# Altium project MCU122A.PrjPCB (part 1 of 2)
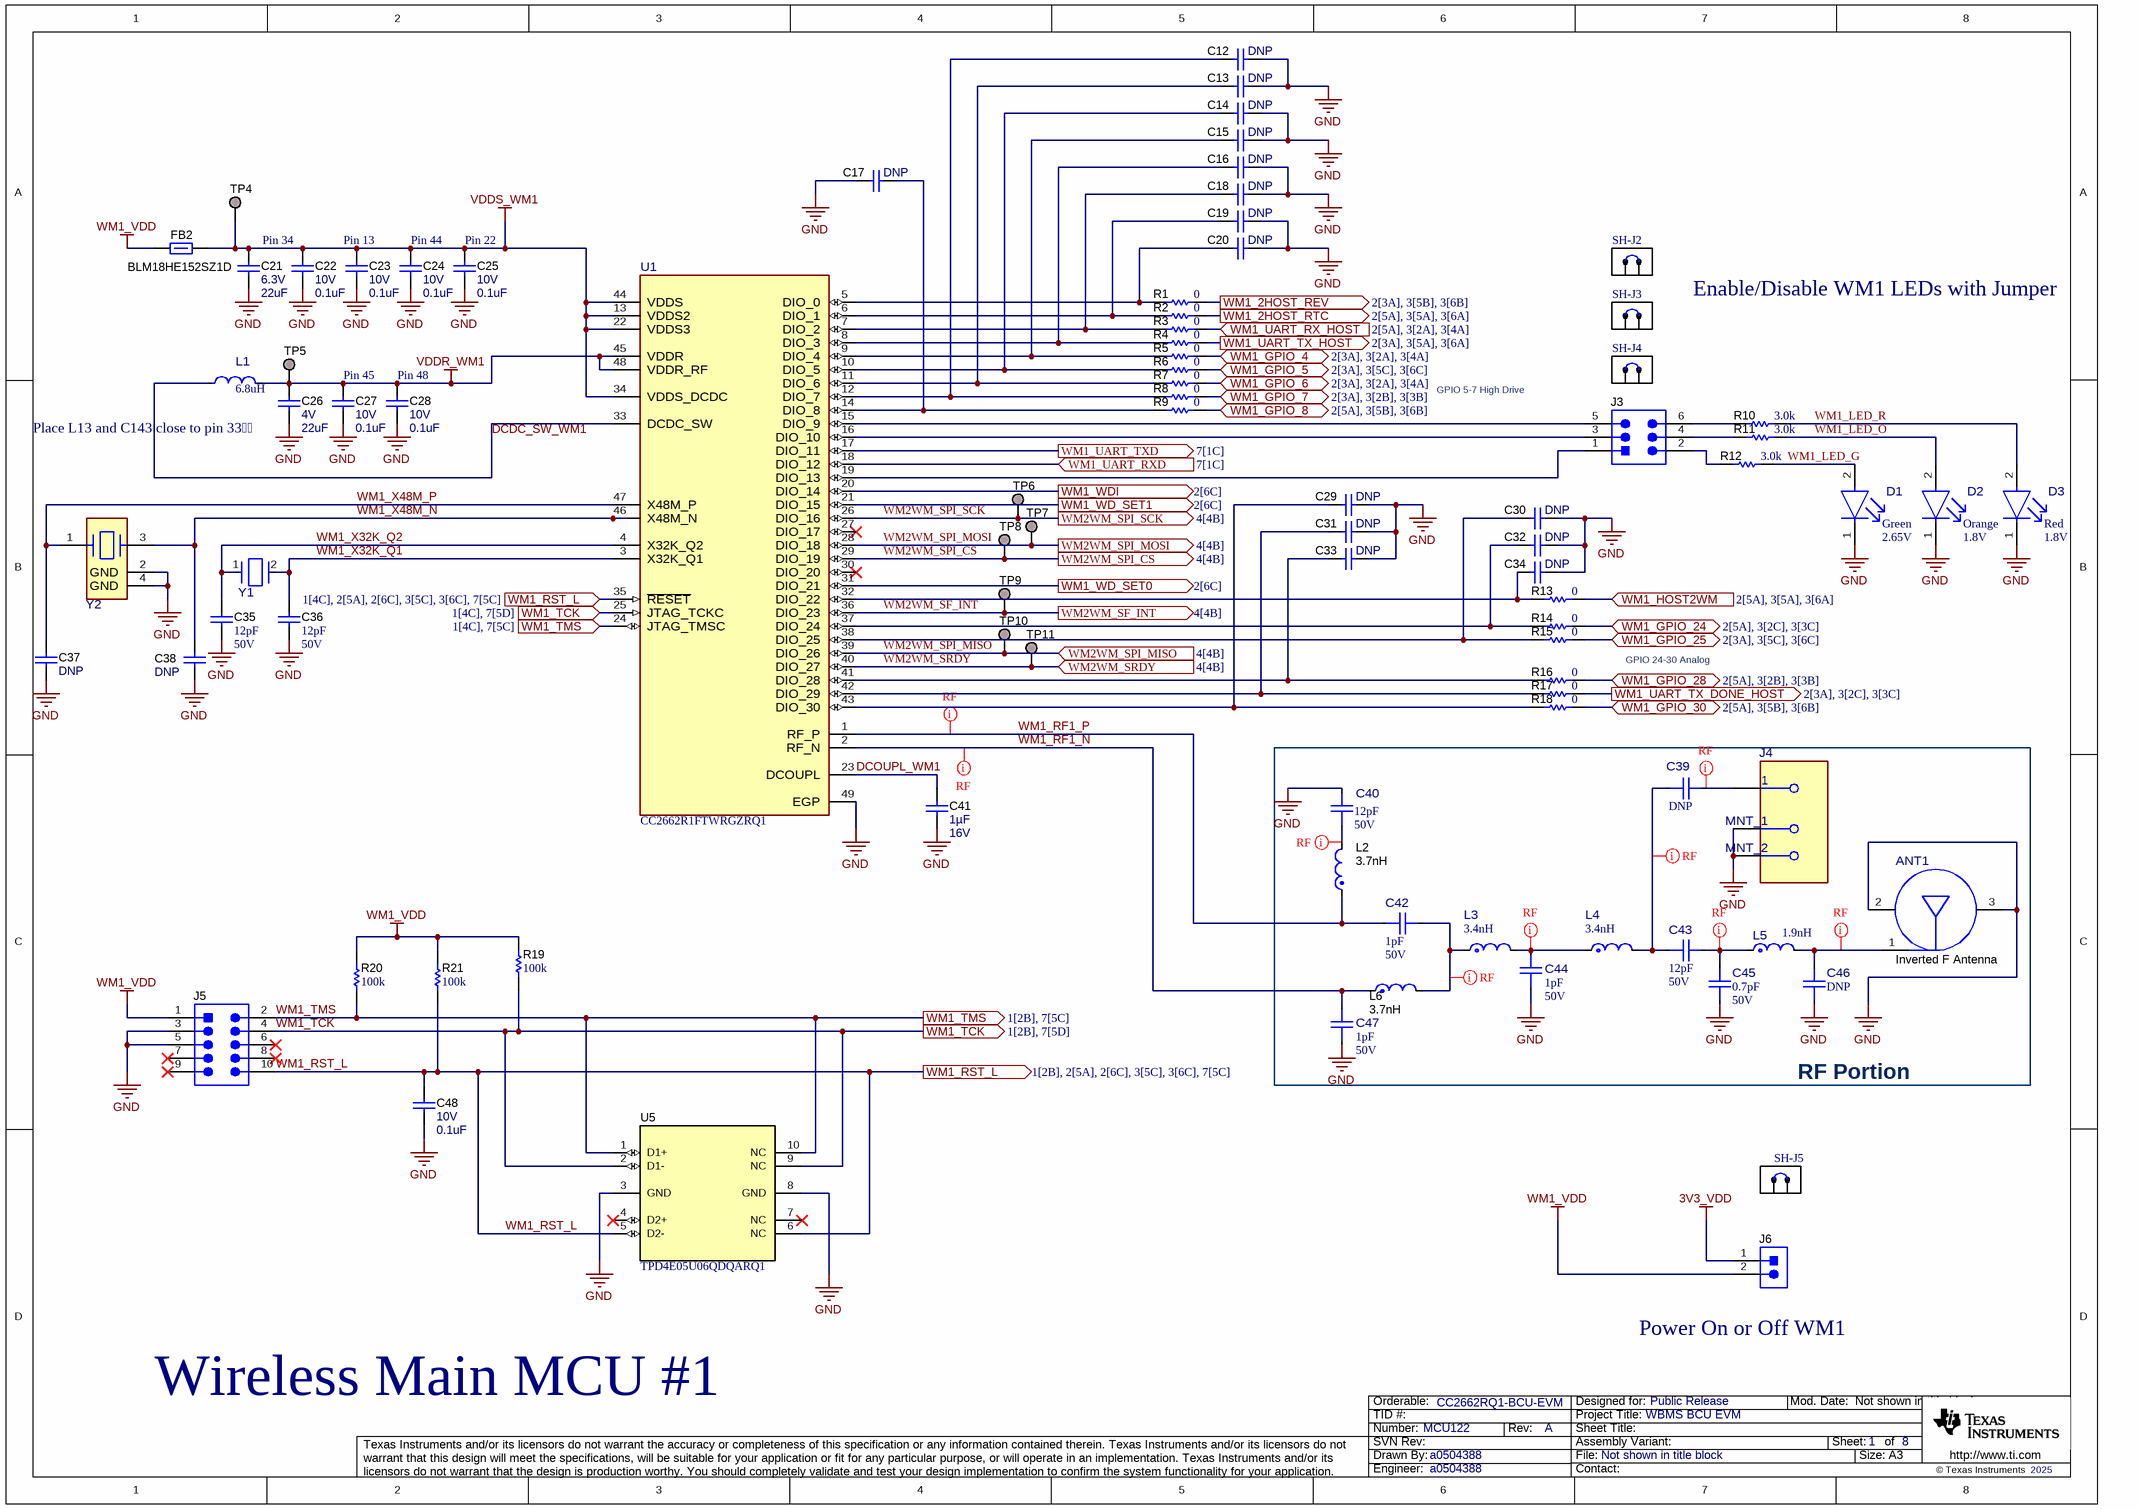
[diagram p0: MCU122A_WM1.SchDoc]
SCH_Rev: A; PRJ_Title: WBMS BCU EVM; PRJ_Number: MCU122; PRJ_Engineer: a0504388; PRJ_Customer: Public Release; PCB_Rev: A; EVM_orderable: CC2662RQ1-BCU-EVM; DrawnBy: a0504388; CopyrightYear: 2025
8 sheets, 257 parts. Net scope: flat (ports and power ports of the same name join across sheets).
Board file: MCU122A.PcbDoc
Sheets:
  MCU122A_WM1.SchDoc
  MCU122A_WM1_GPIO_Header.SchDoc
  MCU122A_WM1_ESD.SchDoc
  MCU122A_WM2.SchDoc
  MCU122A_WM2_GPIO_Header.SchDoc
  MCU122A_WM2_ESD.SchDoc
  MCU122A_Connector_PWR.SchDoc
  MCU122A_Hardware.SchDoc

## Sheet MCU122A_WM1.SchDoc
size A3; Date: Not shown in title block; ApprovedBy: Not shown in title block; CheckedBy: Not shown in title block; Author: Not shown in title block; CompanyName: Not shown in title block; Engineer: Andrew Lugo; Organization: Not shown in title block; Address1: Not shown in title block; Address2: Not shown in title block; Address3: Not shown in title block; Address4: Not shown in title block; DocumentNumber: 1; Revision: Use project parameter SCH_Rev; SheetNumber: 1; SheetTotal: 8; PageSetup: Record=PageOptions¦CenterHorizontal=True¦CenterVertical=True¦PrintScale=0.69¦XCorrection=1.00¦YCorrection=1.00¦PrintKind=0¦BorderSize=5000000¦LeftOffset=0¦BottomOffset=0¦Orientation=2¦PaperLength=1000¦PaperWidth=1000¦Scale=100¦PaperSource=15¦PrintQuality=600¦MediaType=1¦DitherType=10¦PaperKind=Letter¦PrintScaleMode=1

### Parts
ANT1  Inverted F Antenna  [0-MFG]
C12  ValueDisplayed: DNP  [0402]  (hidden comment: GCM155R71A104KA55D)
C13  ValueDisplayed: DNP  [0402]  (hidden comment: GCM155R71A104KA55D)
C14  ValueDisplayed: DNP  [0402]  (hidden comment: GCM155R71A104KA55D)
C15  ValueDisplayed: DNP  [0402]  (hidden comment: GCM155R71A104KA55D)
C16  ValueDisplayed: DNP  [0402]  (hidden comment: GCM155R71A104KA55D)
C17  ValueDisplayed: DNP  [0402]  (hidden comment: GCM155R71A104KA55D)
C18  ValueDisplayed: DNP  [0402]  (hidden comment: GCM155R71A104KA55D)
C19  ValueDisplayed: DNP  [0402]  (hidden comment: GCM155R71A104KA55D)
C20  ValueDisplayed: DNP  [0402]  (hidden comment: GCM155R71A104KA55D)
C21  VDC_V: 6.3V  ValueDisplayed: 22uF  [0805_HV]  (hidden comment: GCM21BD70J226ME36L)
C22  VDC_V: 10V  ValueDisplayed: 0.1uF  [0402]  (hidden comment: GCM155R71A104KA55D)
C23  VDC_V: 10V  ValueDisplayed: 0.1uF  [0402]  (hidden comment: GCM155R71A104KA55D)
C24  VDC_V: 10V  ValueDisplayed: 0.1uF  [0402]  (hidden comment: GCM155R71A104KA55D)
C25  VDC_V: 10V  ValueDisplayed: 0.1uF  [0402]  (hidden comment: GCM155R71A104KA55D)
C26  VDC_V: 4V  ValueDisplayed: 22uF  [0603]  (hidden comment: AMK107BBJ226MAHT)
C27  VDC_V: 10V  ValueDisplayed: 0.1uF  [0402]  (hidden comment: GCM155R71A104KA55D)
C28  VDC_V: 10V  ValueDisplayed: 0.1uF  [0402]  (hidden comment: GCM155R71A104KA55D)
C29  ValueDisplayed: DNP  [0402]  (hidden comment: GCM155R71A104KA55D)
C30  ValueDisplayed: DNP  [0402]  (hidden comment: GCM155R71A104KA55D)
C31  ValueDisplayed: DNP  [0402]  (hidden comment: GCM155R71A104KA55D)
C32  ValueDisplayed: DNP  [0402]  (hidden comment: GCM155R71A104KA55D)
C33  ValueDisplayed: DNP  [0402]  (hidden comment: GCM155R71A104KA55D)
C34  ValueDisplayed: DNP  [0402]  (hidden comment: GCM155R71A104KA55D)
C35  ValueDisplayed: 12pF  VDC_V: 50V  [0402]  (hidden comment: GCM1555C1H120JA16J)
C36  ValueDisplayed: 12pF  VDC_V: 50V  [0402]  (hidden comment: GCM1555C1H120JA16J)
C37  ValueDisplayed: DNP  [0402]  (hidden comment: GCM1555C1H120JA16J)
C38  ValueDisplayed: DNP  [0402]  (hidden comment: GCM1555C1H120JA16J)
C39  ValueDisplayed: DNP  [FP-GCQ0335C1H1R0BB01D_0201-MFG]  (hidden comment: GCQ0335C1H1R0BB01D)
C40  ValueDisplayed: 12pF  VDC_V: 50V  [FP-GCQ0335C1H120GB01D_0201-MFG]  (hidden comment: GCQ0335C1H120GB01D)
C41  Cap_F: 1µF  VDC_V: 16V  [0603]  (hidden comment: GCM188R71C105KA64D)
C42  ValueDisplayed: 1pF  VDC_V: 50V  [FP-GCQ0335C1H1R0WB01D_0201-MFG]  (hidden comment: GCQ0335C1H1R0WB01D)
C43  ValueDisplayed: 12pF  VDC_V: 50V  [FP-GCQ0335C1H120GB01D_0201-MFG]  (hidden comment: GCQ0335C1H120GB01D)
C44  ValueDisplayed: 1pF  VDC_V: 50V  [FP-GCQ0335C1H1R0WB01D_0201-MFG]  (hidden comment: GCQ0335C1H1R0WB01D)
C45  ValueDisplayed: 0.7pF  VDC_V: 50V  [FP-GCQ0335C1HR70WB01D_0201-MFG]  (hidden comment: GCQ0335C1HR70WB01D)
C46  ValueDisplayed: DNP  [FP-GCQ0335C1H1R0BB01D_0201-MFG]  (hidden comment: GCQ0335C1H1R0BB01D)
C47  ValueDisplayed: 1pF  VDC_V: 50V  [FP-GCQ0335C1H1R0WB01D_0201-MFG]  (hidden comment: GCQ0335C1H1R0WB01D)
C48  VDC_V: 10V  ValueDisplayed: 0.1uF  [0402]  (hidden comment: GCM155R71A104KA55D)
D1  Color: Green  Vf_V: 2.65V  [FP-APHHS1005LZGCK-V_0402-MFG]  (hidden comment: APHHS1005LZGCK-V)
D2  Color: Orange  Vf_V: 1.8V  [FP-APHHS1005LSECK/J4-PF_0402-MFG]  (hidden comment: APHHS1005LSECK/J4-PF)
D3  Color: Red  Vf_V: 1.8V  [FP-APHHS1005LSECK/J3-PF_0402-MFG]  (hidden comment: APHHS1005LSECK/J3-PF)
FB2  BLM18HE152SZ1D  [0603]
J3  TSW-103-07-G-D  [TSW-103-07-G-D]  (value not drawn)
J4  132134-10  [FP-132134-10_SMA-MFG]  (value not drawn)
J5  FTSH-105-01-F-DV-K  [Samtec_FTSH-105-01-x-DV-K]  (value not drawn)
J6  TSW-102-07-G-S  [TSW-102-07-G-S]  (value not drawn)
L1  value 6.8uH  [FP-MLZ2012N6R8LTD25_0805-MFG]  (hidden comment: MLZ2012N6R8LTD25)
L2  value 3.7nH  [FP-LQP03TN3N7BZ2J_0603-MFG]  (hidden comment: LQP03TN3N7BZ2J)
L3  value 3.4nH  [FP-LQP03TN3N4BZ2B_0201 (0603)-MFG]  (hidden comment: LQP03TN3N4BZ2B)
L4  value 3.4nH  [FP-LQP03TN3N4BZ2B_0201 (0603)-MFG]  (hidden comment: LQP03TN3N4BZ2B)
L5  value 1.9nH  [FP-LQP03TN1N9BZ2B_0201 (0603)-MFG]  (hidden comment: LQP03TN1N9BZ2B)
L6  value 3.7nH  [FP-LQP03TN3N7BZ2J_0603-MFG]  (hidden comment: LQP03TN3N7BZ2J)
R1  ValueDisplayed: 0  [0402]  (hidden comment: CRCW04020000Z0ED)
R2  ValueDisplayed: 0  [0402]  (hidden comment: CRCW04020000Z0ED)
R3  ValueDisplayed: 0  [0402]  (hidden comment: CRCW04020000Z0ED)
R4  ValueDisplayed: 0  [0402]  (hidden comment: CRCW04020000Z0ED)
R5  ValueDisplayed: 0  [0402]  (hidden comment: CRCW04020000Z0ED)
R6  ValueDisplayed: 0  [0402]  (hidden comment: CRCW04020000Z0ED)
R7  ValueDisplayed: 0  [0402]  (hidden comment: CRCW04020000Z0ED)
R8  ValueDisplayed: 0  [0402]  (hidden comment: CRCW04020000Z0ED)
R9  ValueDisplayed: 0  [0402]  (hidden comment: CRCW04020000Z0ED)
R10  ValueDisplayed: 3.0k  [0402]  (hidden comment: CRCW04023K00JNED)
R11  ValueDisplayed: 3.0k  [0402]  (hidden comment: CRCW04023K00JNED)
R12  ValueDisplayed: 3.0k  [0402]  (hidden comment: CRCW04023K00JNED)
R13  ValueDisplayed: 0  [0402]  (hidden comment: CRCW04020000Z0ED)
R14  ValueDisplayed: 0  [0402]  (hidden comment: CRCW04020000Z0ED)
R15  ValueDisplayed: 0  [0402]  (hidden comment: CRCW04020000Z0ED)
R16  ValueDisplayed: 0  [0402]  (hidden comment: CRCW04020000Z0ED)
R17  ValueDisplayed: 0  [0402]  (hidden comment: CRCW04020000Z0ED)
R18  ValueDisplayed: 0  [0402]  (hidden comment: CRCW04020000Z0ED)
R19  ValueDisplayed: 100k  [0402]  (hidden comment: AC0402FR-07100KL)
R20  ValueDisplayed: 100k  [0402]  (hidden comment: AC0402FR-07100KL)
R21  ValueDisplayed: 100k  [0402]  (hidden comment: AC0402FR-07100KL)
SH-J2  SNT-100-BK-G  [SNT-100-BK-G]  (value not drawn)
SH-J3  SNT-100-BK-G  [SNT-100-BK-G]  (value not drawn)
SH-J4  SNT-100-BK-G  [SNT-100-BK-G]  (value not drawn)
SH-J5  SNT-100-BK-G  [SNT-100-BK-G]  (value not drawn)
TP4  TP_SM_1MM  [TP_SM_1MM]  (value not drawn)  (no BOM)
TP5  TP_SM_1MM  [TP_SM_1MM]  (value not drawn)  (no BOM)
TP6  TP_SM_1MM  [TP_SM_1MM]  (value not drawn)  (no BOM)
TP7  TP_SM_1MM  [TP_SM_1MM]  (value not drawn)  (no BOM)
TP8  TP_SM_1MM  [TP_SM_1MM]  (value not drawn)  (no BOM)
TP9  TP_SM_1MM  [TP_SM_1MM]  (value not drawn)  (no BOM)
TP10  TP_SM_1MM  [TP_SM_1MM]  (value not drawn)  (no BOM)
TP11  TP_SM_1MM  [TP_SM_1MM]  (value not drawn)  (no BOM)
U1  CC2662R1FTWRGZRQ1  [RGZ0048R-MFG]
U5  TPD4E05U06QDQARQ1  [DQA0010A]
Y1  DST1610A 7BG03276AAC  [FP-DST1610A 7BG03276AAC_SMD2-MFG]  (value not drawn)
Y2  CX2016DB48000C0FRLC1  [FP-CX2016DB48000C0FRLC1_SMT4_2MM05_1MM65-MFG]  (value not drawn)

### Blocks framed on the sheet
RF Portion: ANT1 C39 C40 C42-C47 J4 L2-L6

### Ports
WM1_2HOST_REV (out, see 2[3A], 3[5B], 3[6B]), WM1_2HOST_RTC (out, see 2[5A], 3[5A], 3[6A]), WM1_GPIO_4 (bidir, see 2[3A], 3[2A], 3[4A]), WM1_GPIO_5 (bidir, see 2[3A], 3[5C], 3[6C]), WM1_GPIO_6 (bidir, see 2[3A], 3[2A], 3[4A]), WM1_GPIO_7 (bidir, see 2[3A], 3[2B], 3[3B]), WM1_GPIO_8 (bidir, see 2[5A], 3[5B], 3[6B]), WM1_GPIO_24 (bidir, see 2[5A], 3[2C], 3[3C]), WM1_GPIO_25 (bidir, see 2[3A], 3[5C], 3[6C]), WM1_GPIO_28 (bidir, see 2[5A], 3[2B], 3[3B]), WM1_GPIO_30 (bidir, see 2[5A], 3[5B], 3[6B]), WM1_HOST2WM (in, see 2[5A], 3[5A], 3[6A]), WM1_RST_L (in, see 1[4C], 2[5A], 2[6C], 3[5C], 3[6C], 7[5C]), WM1_RST_L (out, see 1[2B], 2[5A], 2[6C], 3[5C], 3[6C], 7[5C]), WM1_TCK (in, see 1[4C], 7[5D]), WM1_TCK (out, see 1[2B], 7[5D]), WM1_TMS (in, see 1[4C], 7[5C]), WM1_TMS (out, see 1[2B], 7[5C]), WM1_UART_RX_HOST (in, see 2[5A], 3[2A], 3[4A]), WM1_UART_RXD (in, see 7[1C]), WM1_UART_TX_DONE_HOST (out, see 2[3A], 3[2C], 3[3C]), WM1_UART_TX_HOST (out, see 2[3A], 3[5A], 3[6A]), WM1_UART_TXD (out, see 7[1C]), WM1_WD_SET0 (out, see 2[6C]), WM1_WD_SET1 (out, see 2[6C]), WM1_WDI (out, see 2[6C]), WM2WM_SF_INT (out, see 4[4B]), WM2WM_SPI_CS (out, see 4[4B]), WM2WM_SPI_MISO (in, see 4[4B]), WM2WM_SPI_MOSI (out, see 4[4B]), WM2WM_SPI_SCK (out, see 4[4B]), WM2WM_SRDY (in, see 4[4B])

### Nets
3V3_VDD: J6.1
GND: ANT1.2(GND) ANT1.3(GND) C12.1 C13.1 C14.1 C15.1 C16.1 C17.2 C18.1 C19.1 C20.1 C21.2 C22.2 C23.2 C24.2 C25.2 C26.2 C27.2 C28.2 C29.1 C30.1 C31.1 C32.1 C33.1 C34.1 C35.2 C36.2 C37.2 C38.2 C40.2 C41.2 C44.1 C45.1 C46.1 C47.1 C48.2 D1.1(CATHODE) D2.1(CATHODE) D3.1(CATHODE) J4.2(MNT_1) J4.3(MNT_2) J5.3 J5.5 U1.49(EGP) U5.3(GND) U5.8(GND) Y2.2(GND) Y2.4(GND)
VDDR_WM1: C26.1 C27.1 C28.1 L1.2 TP5.1 U1.45(VDDR) U1.48(VDDR_RF)
VDDS_WM1: C21.1 C22.1 C23.1 C24.1 C25.1 FB2.2 TP4.1 U1.13(VDDS2) U1.22(VDDS3) U1.34(VDDS_DCDC) U1.44(VDDS)
WM1_VDD: FB2.1 J5.1 J6.2 R19.2 R20.2 R21.2
DCDC_SW_WM1: L1.1 U1.33(DCDC_SW)
DCOUPL_WM1: C41.1 U1.23(DCOUPL)
WM1_2HOST_REV: R1.2 ; port WM1_2HOST_REV
WM1_2HOST_RTC: R2.2 ; port WM1_2HOST_RTC
WM1_GPIO_4: R5.2 ; port WM1_GPIO_4
WM1_GPIO_5: R6.2 ; port WM1_GPIO_5
WM1_GPIO_6: R7.2 ; port WM1_GPIO_6
WM1_GPIO_7: R8.2 ; port WM1_GPIO_7
WM1_GPIO_8: R9.2 ; port WM1_GPIO_8
WM1_GPIO_24: R14.2 ; port WM1_GPIO_24
WM1_GPIO_25: R15.2 ; port WM1_GPIO_25
WM1_GPIO_28: R16.2 ; port WM1_GPIO_28
WM1_GPIO_30: R18.2 ; port WM1_GPIO_30
WM1_HOST2WM: R13.2 ; port WM1_HOST2WM
WM1_LED_G: D1.2(ANODE) R12.2
WM1_LED_O: D2.2(ANODE) R11.2
WM1_LED_R: D3.2(ANODE) R10.2
WM1_RF1_N: C47.2 L6.1 U1.2(RF_N)
WM1_RF1_P: C42.1 L2.1 U1.1(RF_P)
WM1_RST_L: C48.1 J5.10 R21.1 U1.35(~{RESET}) U5.5(D2-) U5.6(NC) ; port WM1_RST_L
WM1_TCK: J5.4 R19.1 U1.25(JTAG_TCKC) U5.2(D1-) U5.9(NC) ; port WM1_TCK
WM1_TMS: J5.2 R20.1 U1.24(JTAG_TMSC) U5.1(D1+) U5.10(NC) ; port WM1_TMS
WM1_UART_RX_HOST: R3.2 ; port WM1_UART_RX_HOST
WM1_UART_RXD: U1.18(DIO_12) ; port WM1_UART_RXD
WM1_UART_TX_DONE_HOST: R17.2 ; port WM1_UART_TX_DONE_HOST
WM1_UART_TX_HOST: R4.2 ; port WM1_UART_TX_HOST
WM1_UART_TXD: U1.17(DIO_11) ; port WM1_UART_TXD
WM1_WD_SET0: U1.31(DIO_21) ; port WM1_WD_SET0
WM1_WD_SET1: U1.21(DIO_15) ; port WM1_WD_SET1
WM1_WDI: U1.20(DIO_14) ; port WM1_WDI
WM1_X32K_Q1: C36.1 U1.3(X32K_Q1) Y1.2
WM1_X32K_Q2: C35.1 U1.4(X32K_Q2) Y1.1
WM1_X48M_N: C38.1 U1.46(X48M_N) Y2.3
WM1_X48M_P: C37.1 U1.47(X48M_P) Y2.1
WM2WM_SF_INT: TP9.1 U1.36(DIO_23) ; port WM2WM_SF_INT
WM2WM_SPI_CS: TP8.1 U1.29(DIO_19) ; port WM2WM_SPI_CS
WM2WM_SPI_MISO: TP10.1 U1.39(DIO_26) ; port WM2WM_SPI_MISO
WM2WM_SPI_MOSI: TP7.1 U1.28(DIO_18) ; port WM2WM_SPI_MOSI
WM2WM_SPI_SCK: TP6.1 U1.26(DIO_16) ; port WM2WM_SPI_SCK
WM2WM_SRDY: TP11.1 U1.40(DIO_27) ; port WM2WM_SRDY
NetANT1_1: ANT1.1(Feed) C46.2 L5.2
NetC12_2: C12.2 R8.1 U1.12(DIO_7)
NetC13_2: C13.2 R7.1 U1.11(DIO_6)
NetC14_2: C14.2 R6.1 U1.10(DIO_5)
NetC15_2: C15.2 R5.1 U1.9(DIO_4)
NetC16_2: C16.2 R4.1 U1.8(DIO_3)
NetC17_1: C17.1 R9.1 U1.14(DIO_8)
NetC18_2: C18.2 R3.1 U1.7(DIO_2)
NetC19_2: C19.2 R2.1 U1.6(DIO_1)
NetC20_2: C20.2 R1.1 U1.5(DIO_0)
NetC29_2: C29.2 R18.1 U1.43(DIO_30)
NetC30_2: C30.2 R15.1 U1.38(DIO_25)
NetC31_2: C31.2 R17.1 U1.42(DIO_29)
NetC32_2: C32.2 R14.1 U1.37(DIO_24)
NetC33_2: C33.2 R16.1 U1.41(DIO_28)
NetC34_2: C34.2 R13.1 U1.32(DIO_22)
NetC39_1: C39.1 C43.1 L4.2
NetC39_2: C39.2 J4.1
NetC40_1: C40.1 L2.2
NetC42_2: C42.2 L3.1 L6.2
NetC43_2: C43.2 C45.2 L5.1
NetC44_2: C44.2 L3.2 L4.1
NetJ3_1: J3.1 U1.19(DIO_13)
NetJ3_2: J3.2 R12.1
NetJ3_3: J3.3 U1.16(DIO_10)
NetJ3_4: J3.4 R11.1
NetJ3_5: J3.5 U1.15(DIO_9)
NetJ3_6: J3.6 R10.1

Not connected (* = marked no-connect by the designer): J5 6* 7* 8* 9*; U1 27(DIO_17)* 30(DIO_20)*; U5 4(D2+)* 7(NC)*

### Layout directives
net class RF: NetANT1_1, NetC39_1, NetC39_2, NetC40_1, NetC42_2, NetC43_2, NetC44_2, WM1_RF1_N, WM1_RF1_P

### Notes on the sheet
- Pin 34
- (near C23) Pin 13
- Pin 44
- (near C25) Pin 22
- Enable/Disable WM1 LEDs with Jumper
- Pin 45
- (near C28) Pin 48
- (near C26) Place L13 and C143 close to pin 33
- GPIO 5-7 High Drive
- GPIO 24-30 Analog
- (near J6) Power On or Off WM1
- Wireless Main MCU #1

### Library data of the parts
ANT1 = CMP-0091830-1: 2.4-GHz Inverted F Antenna; Manufacturer: Texas Instruments; AEC Qualified: No; Number Of Bands: 1
C12-C20 C29-C34 = CMP-0006350-2: CAP, CERM, 0.1 uF, 10 V, +/- 10%, X7R, AEC-Q200 Grade 1, 0402; Manufacturer: MuRata; TaMin_C: -55°C; Polarized: N; SizeAreaWB_mm2: 3; Value1: Unknown; U/M: EA; Value: 0.1uF; TaMax_C: 125°C; SizeZ_mm: 0.6; SizeX_mm: 1; SizeY_mm: 0.5; Value2: 10V; AEC Qualified: Y; Cap_F: 100nF; AEC Category: Q200
C21 = CMP-0008015-1: CAP, CERM, 22 uF, 6.3 V, +/- 20%, X7T, AEC-Q200 Grade 1, 0805; Manufacturer: MuRata; TaMin_C: -55°C; Polarized: N; SizeAreaWB_mm2: 6.75; Value1: Unknown; U/M: EA; Value: 22uF; TaMax_C: 125°C; SizeZ_mm: 1.45; SizeX_mm: 2; SizeY_mm: 1.25; Cap_Case: 0805; SizeArea_mm2: 2.5; AEC Qualified: Y; Cap_F: 22µF; AEC Grade: 1; AEC Category: Q200
C22-C25 C27 C28 C48 = CMP-0006350-2: CAP, CERM, 0.1 uF, 10 V, +/- 10%, X7R, AEC-Q200 Grade 1, 0402; Manufacturer: MuRata; TaMin_C: -55°C; Polarized: N; SizeAreaWB_mm2: 3; Value1: Unknown; U/M: EA; Value: 0.1uF; TaMax_C: 125°C; SizeZ_mm: 0.6; SizeX_mm: 1; SizeY_mm: 0.5; AEC Qualified: Y; Cap_F: 100nF; AEC Category: Q200
C26 = CMP-0064940-5: CAP, CERM, 22 uF, 4 V,+/- 20%, X5R, AEC-Q200 Grade 3, 0603; Manufacturer: Taiyo Yuden; TaMin_C: -55°C; Polarized: N; SizeAreaWB_mm2: 4.68; Value1: Unknown; U/M: EA; Value: 22uF; TaMax_C: 85°C; SizeZ_mm: 1; SizeX_mm: 1.6; SizeY_mm: 0.8; SizeArea_mm2: 1.28; AEC Qualified: Y; Cap_F: 22µF; AEC Grade: 3; AEC Category: Q200
C35 C36 = CMP-0085816-1: CAP, CERM, 12 pF, 50 V,+/- 5%, C0G/NP0, AEC-Q200 Grade 1, 0402; Manufacturer: MuRata; AEC Category: Q200; SizeX_mm: 1; TaMin_C: -55°C; SizeAreaWB_mm2: 3; SizeArea_mm2: 0.5; SizeZ_mm: 0.6; Polarized: N; U/M: EA; Value: 12pF; TaMax_C: 125°C; AEC Qualified: Y
C37 C38 = CMP-0085816-1: CAP, CERM, 12 pF, 50 V,+/- 5%, C0G/NP0, AEC-Q200 Grade 1, 0402; Manufacturer: MuRata; AEC Category: Q200; SizeX_mm: 1; TaMin_C: -55°C; Value2: 50V; Cap_F: 12pF; SizeAreaWB_mm2: 3; SizeArea_mm2: 0.5; SizeZ_mm: 0.6; Polarized: N; U/M: EA; Value: 12pF; TaMax_C: 125°C; AEC Qualified: Y
C39 C46 = CMP-0037173-1: 1pF ±0.1pF 50V Ceramic Capacitor C0G 0201 (0603 Metric); Manufacturer: Murata; AEC Grade: Grade 1; AEC Qualified: Yes; SizeZ_mm: 0.33mm; TempCo: 30ppm/°C
C40 C43 = CMP-0120430-1: High Q Chip Multilayer Ceramic Capacitors for Automotive 12pF ±2% 50Vdc 0201; Manufacturer: Murata; AEC Grade: Grade 1; AEC Qualified: Yes; SizeZ_mm: 0.33mm; TempCo: 30ppm/°C; Temperature Characteristic: C0G
C41 = CMP-0007136-5: CAP, CERM, 1 uF, 16 V, +/- 10%, X7R, AEC-Q200 Grade 1, 0603; Manufacturer: MuRata; TaMin_C: -55°C; Polarized: N; SizeAreaWB_mm2: 4.68; Value1: Unknown; U/M: EA; Value: 1uF; TaMax_C: 125°C; SizeZ_mm: 1; SizeX_mm: 1.6; SizeY_mm: 0.8; SizeArea_mm2: 1.28; AEC Qualified: Y; AEC Category: Q200
C42 C44 C47 = CMP-0120431-1: 1pF ±0.05pF 50V Ceramic Capacitor C0G 0201 (0603 Metric); Manufacturer: Murata; AEC Grade: Grade 1; AEC Qualified: Yes; SizeZ_mm: 0.33mm; TempCo: 30ppm/°C
C45 = CMP-0124488-1: Cap Ceramic 0.7pF ±0.05pF 50V C0G 0201 AECQ200; Manufacturer: Murata; AEC Grade: Grade 1; AEC Qualified: Yes; SizeZ_mm: 0.33mm; TempCo: 30ppm/°C
D1 = CMP-0120353-1: Green 525nm LED Indication - Discrete 2.65V 0402 (1005 Metric); Manufacturer: Kingbright; Angle: 140°; LambdaP: 515nm; Power_TotalModule: 102.5mW; SizeZ_mm: 0.6mm; Vr_V: 5V; AEC Qualified: No; Forward Current: 2mA; Led Orientation: Top View; Luminous Intensity: 40mcd
D2 = CMP-0120352-1: LED Uni-Color SB. Orange 611nm 2-Pin SMD T/R; Manufacturer: Kingbright; Angle: 120°; LambdaD: 605nm; Power_TotalModule: 84mW; SizeZ_mm: 0.6mm; Tjmax_C: 115°C; Vr_V: 5V; AEC Qualified: No; Forward Current: 2mA; Led Orientation: Top View; Luminous Intensity: 40mcd
D3 = CMP-0120351-1: Red 625nm LED Indication - Discrete 1.8V 0402 (1005 Metric); Manufacturer: Kingbright; Angle: 120°; LambdaP: 640nm; Power_TotalModule: 84mW; SizeZ_mm: 0.6mm; Vr_V: 5V; AEC Qualified: No; Forward Current: 2mA; Led Orientation: Top View; Luminous Intensity: 35mcd
FB2 = CMP-0080768-1: Ferrite Bead, 1500 ohm @ 100 MHz, 0.5 A, 0603; Manufacturer: MuRata; SizeAreaWB_mm2: 4.68; SizeArea_mm2: 1.28; SizeZ_mm: 1; Imax_A: 5dA; ZTyp@100MHz_Ohm: 1.5k; SizeY_mm: 0.8; Value2: 0.5A; Value1: 0.5 ohm; DCR_ohm: 5d; SizeX_mm: 1.6
J3 = CMP-0075406-2: Header, 100mil, 3x2, Gold, TH; Manufacturer: Samtec; Pitch_mm: 2.54; Cert_VDE: N; Gender: Male; Cert_CSA: Y; Voltage_V: 550V; Green_REACh: Passed; Current_A: 6.3A; Green_Lifecycle: Active; Row_Count: 2
J4 = CMP-0035654-1: SMA PCB Surface Mount Jack 50 Ohm; Manufacturer: Amphenol Connex; ContactFinish: Gold; Shrouded: true; AEC Qualified: No; Conn Orientation: Straight; Dielectric Material: PTFE; Frequency_Fixed: 18GHz; Impedance: 50Ω; Is Female: yes; SizeZ_mm: 9.24mm; Standoff Height: 0mm
J5 = CMP-0075670-2: Header (Shrouded), 1.27mm, 5x2, Gold, SMT; Manufacturer: Samtec; Pitch_mm: 1.27; Gender: Male; Cert_CSA: Y; Current_A: 3.3A; Row_Count: 2
J6 = CMP-0075405-3: Header, 100mil, 2x1, Gold, TH; Manufacturer: Samtec; Current_A: 6.3A; Green_Lifecycle: Active; Pitch_mm: 2.54; Cert_CSA: Y; Cert_VDE: N; Green_REACh: Passed; Row_Count: 1; Gender: Male; Voltage_V: 550V
L1 = CMP-0121210-1: Shielded Multilayer Inductor 6.8uH ±20% 550mA 325mΩ AEC-Q200 SMD 0805; Manufacturer: TDK; AEC Grade: Grade 1; AEC Qualified: Yes; DCR_ohm: 0.325; Ind_H: 6.8µH; Isat: 110mA; Material: Ferrite; SizeZ_mm: 1.05mm; Shrouded: true; Test Frequency: 2MHz
L2 L6 = CMP-0090225-1: Inductor 3.7nH, Size Code 0603 (0201), High Q, Wide Variation. AEC-Q200; Manufacturer: Murata; DCR_ohm: 0.3; AEC Qualified: Yes; TaMax_C: +125°C; Q Factor: 14; Tolerance_%: 0.1nH; Self Resonant Frequency: 6GHz; AEC Grade: Grade 1; TaMin_C: -55°C; Test Frequency: 500MHz; Irms: 400mA; SizeZ_mm: 0.33mm
L3 L4 = CMP-0037178-1: Film type RF Inductor for Automotive 3.4nH ±0.1nH 450mA 0.25Ω 0201 (0603); Manufacturer: Murata; AEC Grade: Grade 1; AEC Qualified: Yes; DCR_ohm: 0.25; SizeZ_mm: 0.33mm; Q Factor: 14; Self Resonant Frequency: 7GHz; Test Frequency: 500MHz
L5 = CMP-0124484-1: Film type RF Inductor for Automotive 1.9nH ±0.1nH 600mA 0.15Ω 0201 (0603); Manufacturer: Murata; AEC Grade: Grade 1; AEC Qualified: Yes; DCR_ohm: 0.15; SizeZ_mm: 0.33mm; Q Factor: 14; Self Resonant Frequency: 12.5GHz; Test Frequency: 500MHz
R1-R9 R13-R18 = CMP-0026822-3: RES, 0, 5%, 0.063 W, AEC-Q200 Grade 0, 0402; Manufacturer: Vishay-Dale; Power_W: 63mW; TempCo: 200 ppm/C; Value_Code: 0000; Value: 0; EIA_Code: E24; SizeX_mm: 1; SizeY_mm: 0.5; SizeZ_mm: 0.6; Value2: 0.063W; AEC Qualified: Y; VDC_V: 50V; AEC Category: Q200
R10-R12 = CMP-0026917-5: RES, 3.0 k, 5%, 0.063 W, AEC-Q200 Grade 0, 0402; Manufacturer: Vishay-Dale; Power_W: 63mW; TempCo: 200 ppm/C; Value_Code: 3k00; Value: 3.0k; EIA_Code: E24; Res_ohm: 3k; SizeX_mm: 1; SizeY_mm: 0.5; SizeZ_mm: 0.6; Value2: 0.063W; AEC Qualified: Y; VDC_V: 50V; AEC Category: Q200; AEC Grade: 0
R19-R21 = CMP-0080661-1: RES, 100 k, 1%, 0.0625 W, AEC-Q200 Grade 0, 0402; Manufacturer: Yageo America; Power_W: 62.5mW; TempCo: 100 ppm/C; SizeAreaWB_mm2: 3; Value: 100k; EIA_Code: E96; SizeX_mm: 1; SizeY_mm: 0.5; SizeZ_mm: 0.6; AEC Qualified: Y; VDC_V: 50V; AEC Grade: 0; AEC Category: Q200
SH-J2-SH-J5 = CMP-0003623-3: Shunt, 100mil, Gold plated, Black; Alternate PartNumber: 969102-0000-DA; Manufacturer: Samtec; Alternate Manufacturer: 3M; Value: 1x2; Note: You can "mate" this to a header by matching the designator.  i.e. use SH-J3 for header J3
TP4-TP11 = CMP-0003825-1: 1mm Test Point, SMT; Manufacturer: Any
U1 = CMP-0121950-1: Automotive qualified SimpleLink wireless MCU for use in wireless battery management systems; Manufacturer: Texas Instruments; SizeZ_mm: 1mm; AEC Qualified: Yes; AEC Grade: Grade 2; Core Architecture: ARM Cortex-M4F; Data Bus Width: 32bits; Frequency_Fixed: 48MHz; Interface: I2C,SPI,UART,I2S; Max Supply Voltage: 3.63V; Memory Size: 352KBytes; Memory Type: FLASH; Min Supply Voltage: 1.8V; Number Of A/D Converters: 1; Number Of Adc Channels: 8; Number Of I/Os: 31; Number Of Pwm Channels: 9; Number Of Spi Channels: 2; Number Of Timers/Counters: 11; Ram Size: 80KBytes; Standoff Height: 0mm; TaMax_C: +105°C; TaMin_C: -40°C
U5 = CMP-0073599-3: Automotive 4-Channel ESD Protection Solution for SuperSpeed (up to 5 Gbps) Interface, DQA0010A (USON-10); Manufacturer: Texas Instruments; SizeZ_mm: 0.55; SizeX_mm: 1.0; SizeY_mm: 2.5; CompType: IC; SizeAreaWB_mm2: 7.0; AEC Category: Q200; AEC Qualified: Y
Y1 = CMP-0121920-1: SMD Tuning Fork Crystal Resonators / kHz Band Crystal Resonators 32.768KHZ 7PF ±20PPM; Manufacturer: DAISHINKU; SizeZ_mm: 0.5mm; AEC Qualified: Yes; AEC Grade: Grade 1; Esr: 70k; TJmax_C: +125°C
Y2 = CMP-0121714-1: Quartz Crystal 48 MHz 7pF 10ppm; Manufacturer: KYOCERA AVX; Frequency Stability: 20ppm; Frequency_Fixed: 48MHz; SizeZ_mm: 0.5mm; AEC Qualified: Yes; AEC Grade: Grade 2; Esr: 30

## Sheet MCU122A_WM1_GPIO_Header.SchDoc
size A3; Date: Not shown in title block; ApprovedBy: Not shown in title block; CheckedBy: Not shown in title block; Author: Not shown in title block; CompanyName: Not shown in title block; Engineer: Andrew Lugo; Organization: Not shown in title block; Address1: Not shown in title block; Address2: Not shown in title block; Address3: Not shown in title block; Address4: Not shown in title block; DocumentNumber: 1; Revision: Use project parameter SCH_Rev; SheetNumber: 2; SheetTotal: 8; PageSetup: Record=PageOptions¦CenterHorizontal=True¦CenterVertical=True¦PrintScale=0.69¦XCorrection=1.00¦YCorrection=1.00¦PrintKind=0¦BorderSize=5000000¦LeftOffset=0¦BottomOffset=0¦Orientation=2¦PaperLength=1000¦PaperWidth=1000¦Scale=100¦PaperSource=15¦PrintQuality=600¦MediaType=1¦DitherType=10¦PaperKind=Letter¦PrintScaleMode=1
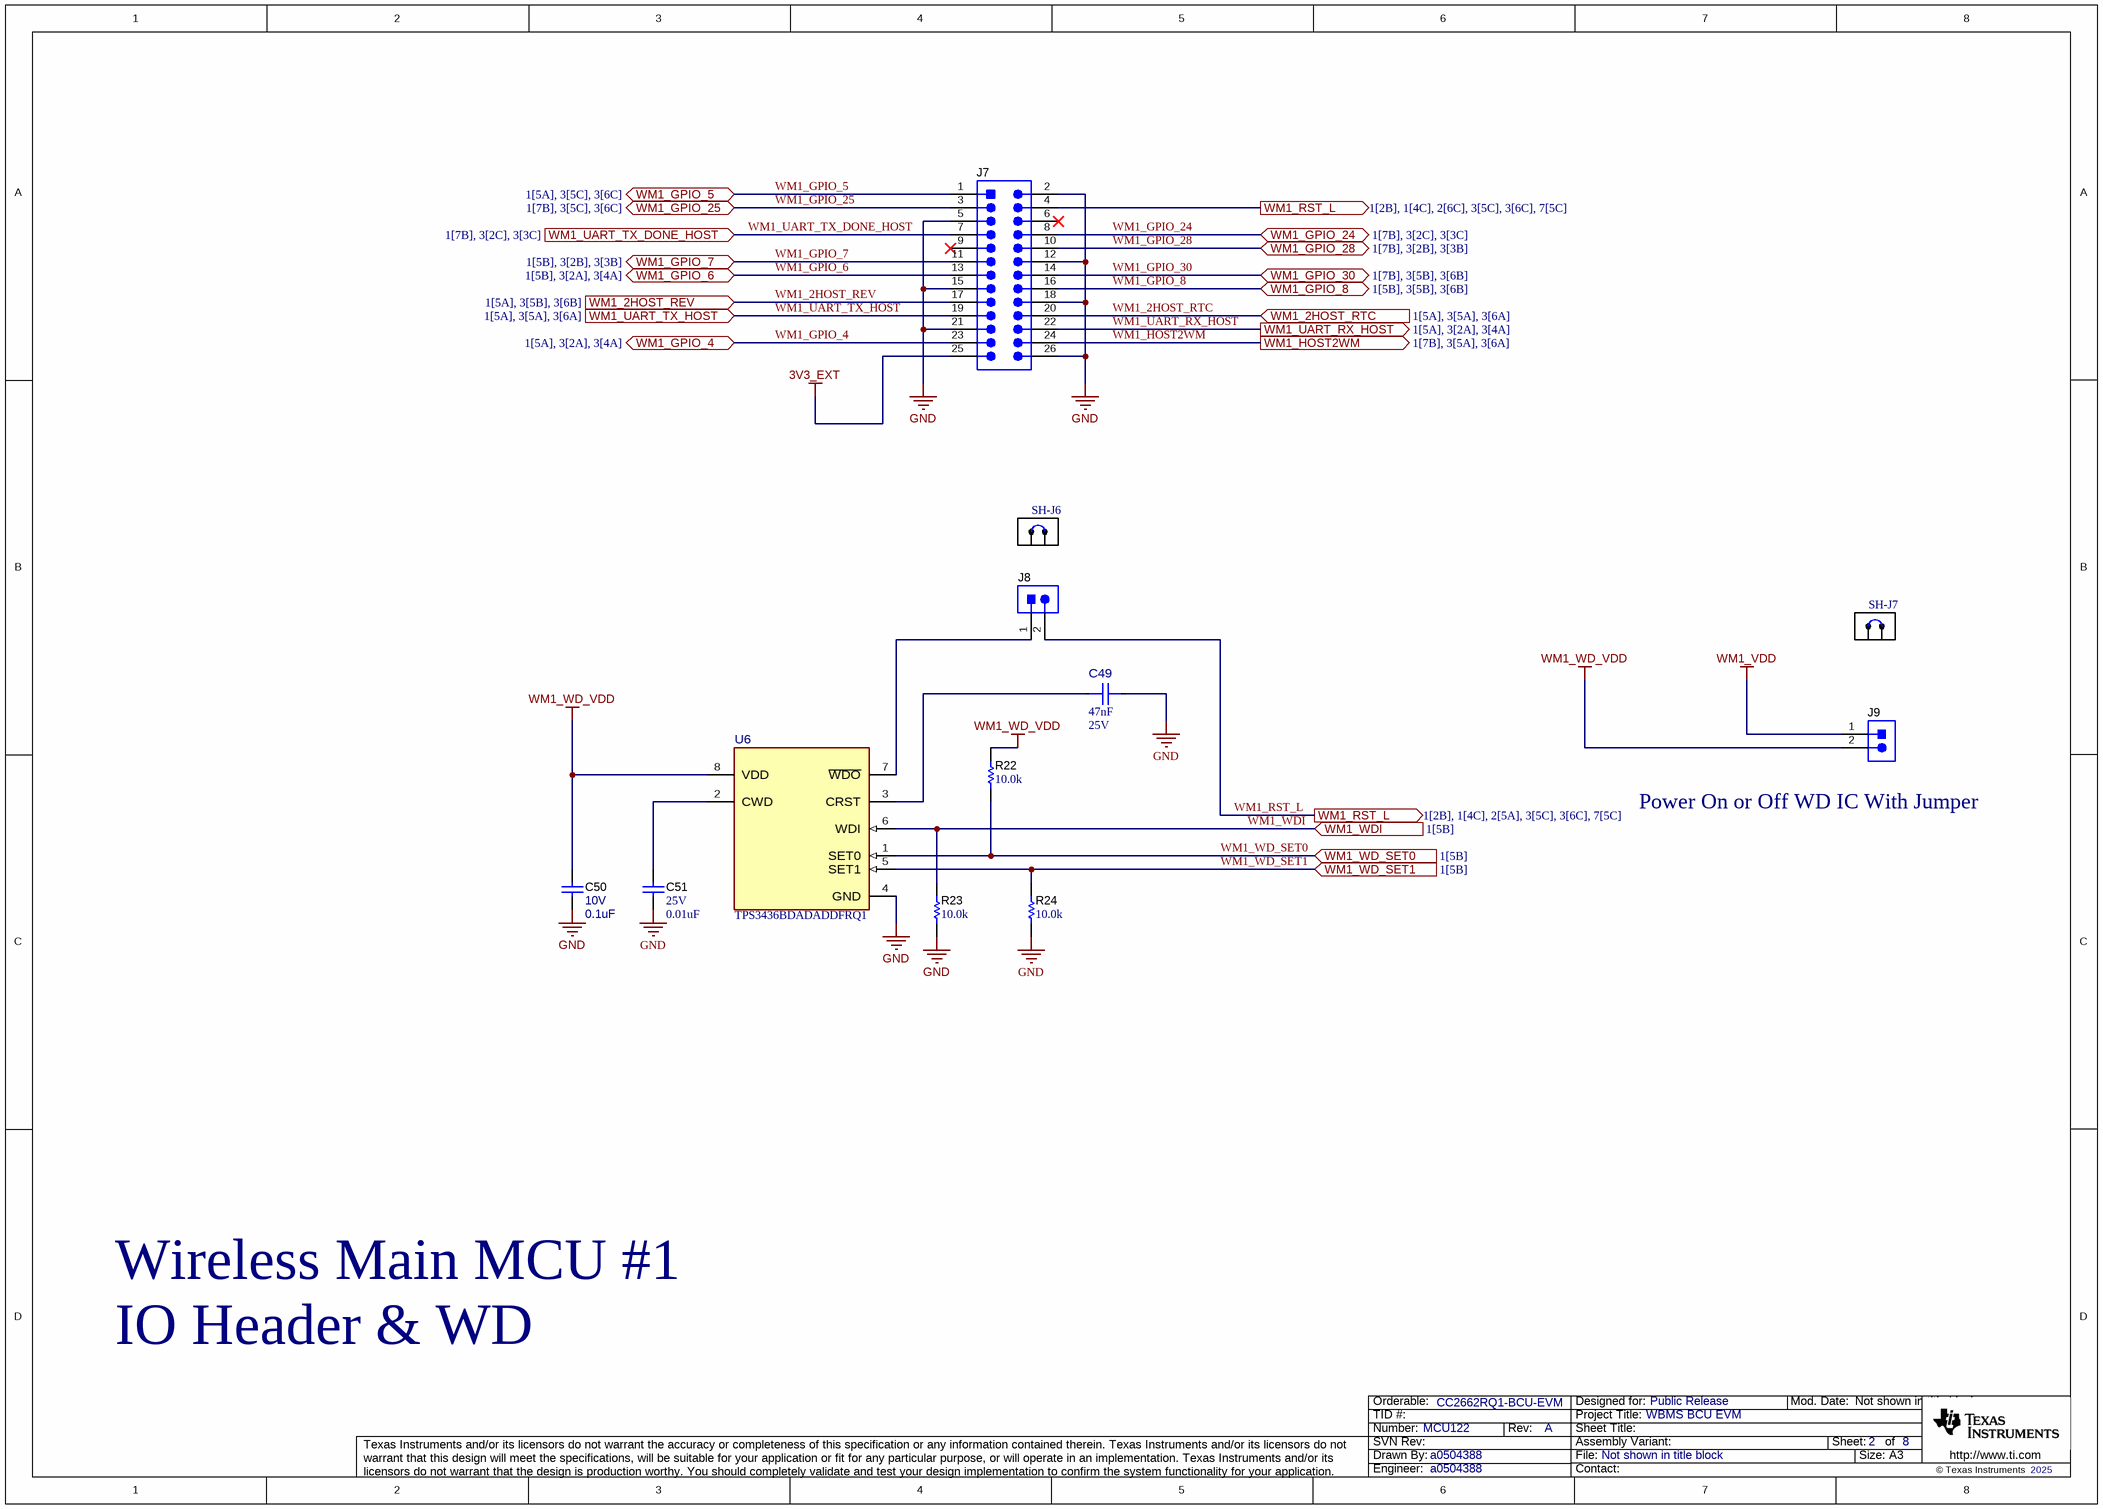
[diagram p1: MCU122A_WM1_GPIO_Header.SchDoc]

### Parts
C49  ValueDisplayed: 47nF  VDC_V: 25V  [FP-GCM155R71E473KA55D_0402-MFG]  (hidden comment: GCM155R71E473KA55D)
C50  VDC_V: 10V  ValueDisplayed: 0.1uF  [0402]  (hidden comment: GCM155R71A104KA55D)
C51  VDC_V: 25V  ValueDisplayed: 0.01uF  [0402]  (hidden comment: GCM155R71E103KA37D)
J7  TSW-113-07-G-D  [TSW-113-07-G-D]  (value not drawn)
J8  TSW-102-07-G-S  [TSW-102-07-G-S]  (value not drawn)
J9  TSW-102-07-G-S  [TSW-102-07-G-S]  (value not drawn)
R22  ValueDisplayed: 10.0k  [0402]  (hidden comment: AC0402FR-0710KL)
R23  ValueDisplayed: 10.0k  [0402]  (hidden comment: AC0402FR-0710KL)
R24  ValueDisplayed: 10.0k  [0402]  (hidden comment: AC0402FR-0710KL)
SH-J6  SNT-100-BK-G  [SNT-100-BK-G]  (value not drawn)
SH-J7  SNT-100-BK-G  [SNT-100-BK-G]  (value not drawn)
U6  TPS3436BDADADDFRQ1  [DDF0008A-MFG]

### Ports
WM1_2HOST_REV (in, see 1[5A], 3[5B], 3[6B]), WM1_2HOST_RTC (in, see 1[5A], 3[5A], 3[6A]), WM1_GPIO_4 (bidir, see 1[5A], 3[2A], 3[4A]), WM1_GPIO_5 (bidir, see 1[5A], 3[5C], 3[6C]), WM1_GPIO_6 (bidir, see 1[5B], 3[2A], 3[4A]), WM1_GPIO_7 (bidir, see 1[5B], 3[2B], 3[3B]), WM1_GPIO_8 (bidir, see 1[5B], 3[5B], 3[6B]), WM1_GPIO_24 (bidir, see 1[7B], 3[2C], 3[3C]), WM1_GPIO_25 (bidir, see 1[7B], 3[5C], 3[6C]), WM1_GPIO_28 (bidir, see 1[7B], 3[2B], 3[3B]), WM1_GPIO_30 (bidir, see 1[7B], 3[5B], 3[6B]), WM1_HOST2WM (out, see 1[7B], 3[5A], 3[6A]), WM1_RST_L (out, see 1[2B], 1[4C], 2[5A], 3[5C], 3[6C], 7[5C]), WM1_RST_L (out, see 1[2B], 1[4C], 2[6C], 3[5C], 3[6C], 7[5C]), WM1_UART_RX_HOST (out, see 1[5A], 3[2A], 3[4A]), WM1_UART_TX_DONE_HOST (in, see 1[7B], 3[2C], 3[3C]), WM1_UART_TX_HOST (in, see 1[5A], 3[5A], 3[6A]), WM1_WD_SET0 (in, see 1[5B]), WM1_WD_SET1 (in, see 1[5B]), WM1_WDI (in, see 1[5B])

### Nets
3V3_EXT: J7.25
GND: C49.2 C50.2 C51.2 J7.2 J7.5 J7.12 J7.15 J7.18 J7.21 J7.26 R23.1 R24.1 U6.4(GND)
WM1_VDD: J9.1
WM1_WD_VDD: C50.1 J9.2 R22.2 U6.8(VDD)
WM1_2HOST_REV: J7.17 ; port WM1_2HOST_REV
WM1_2HOST_RTC: J7.20 ; port WM1_2HOST_RTC
WM1_GPIO_4: J7.23 ; port WM1_GPIO_4
WM1_GPIO_5: J7.1 ; port WM1_GPIO_5
WM1_GPIO_6: J7.13 ; port WM1_GPIO_6
WM1_GPIO_7: J7.11 ; port WM1_GPIO_7
WM1_GPIO_8: J7.16 ; port WM1_GPIO_8
WM1_GPIO_24: J7.8 ; port WM1_GPIO_24
WM1_GPIO_25: J7.3 ; port WM1_GPIO_25
WM1_GPIO_28: J7.10 ; port WM1_GPIO_28
WM1_GPIO_30: J7.14 ; port WM1_GPIO_30
WM1_HOST2WM: J7.24 ; port WM1_HOST2WM
WM1_RST_L: J7.4 J8.2 ; port WM1_RST_L
WM1_UART_RX_HOST: J7.22 ; port WM1_UART_RX_HOST
WM1_UART_TX_DONE_HOST: J7.7 ; port WM1_UART_TX_DONE_HOST
WM1_UART_TX_HOST: J7.19 ; port WM1_UART_TX_HOST
WM1_WD_SET0: R22.1 U6.1(SET0) ; port WM1_WD_SET0
WM1_WD_SET1: R24.2 U6.5(SET1) ; port WM1_WD_SET1
WM1_WDI: R23.2 U6.6(WDI) ; port WM1_WDI
NetC49_1: C49.1 U6.3(CRST)
NetC51_1: C51.1 U6.2(CWD)
NetJ8_1: J8.1 U6.7(~{WDO})

Not connected (* = marked no-connect by the designer): J7 6* 9*

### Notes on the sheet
- (near J9) Power On or Off WD IC With Jumper
- Wireless Main MCU #1 IO Header & WD

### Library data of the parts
C49 = CMP-0120705-1: Ceramic Capacitor for Automotive 47nF ±10% 25VDC X7R 0402 Paper T/R; Manufacturer: Murata; AEC Grade: Grade 1; AEC Qualified: Yes; SizeZ_mm: 0.55mm; TempCo: 15%; Tolerance_%: 0.1%
C50 = CMP-0006350-2: as C22 on sheet MCU122A_WM1
C51 = CMP-0006352-2: CAP, CERM, 0.01 uF, 25 V, +/- 10%, X7R, 0402; Manufacturer: MuRata; TaMin_C: -55°C; Polarized: N; SizeAreaWB_mm2: 3; Value1: Unknown; U/M: EA; Value: 0.01uF; TaMax_C: 125°C; SizeZ_mm: 0.6; SizeX_mm: 1; SizeY_mm: 0.5; Cap_F: 10nF; AEC Category: Q200
J7 = CMP-0075425-1: Header, 100mil, 13x2, Gold, TH; Manufacturer: Samtec; Pitch_mm: 2.54; Cert_VDE: N; Gender: Male; Cert_CSA: Y; Voltage_V: 550V; Green_REACh: Passed; Current_A: 6.3A; CT: False; Green_Lifecycle: Active; Row_Count: 2; CNHeader: True
J8 J9 = CMP-0075405-3: as J6 on sheet MCU122A_WM1
R22-R24 = CMP-0077731-1: RES, 10.0 k, 1%, 0.063 W, AEC-Q200 Grade 0, 0402; Manufacturer: Yageo America; Power_W: 63mW; TempCo: 100 ppm/C; Value_Code: 10k0; U/M: EA; Value: 10.0k; EIA_Code: E96; Res_ohm: 10k; SizeX_mm: 1.0; SizeY_mm: 0.5; SizeZ_mm: 0.6; Value2: 0.063W; AEC Qualified: Y; VDC_V: 50V; AEC Grade: 0; AEC Category: Q200
SH-J6 SH-J7 = CMP-0003623-3: as SH-J2 on sheet MCU122A_WM1
U6 = CMP-0120735-1: Automotive Nano IQ Precision Window Watchdog Timer; Manufacturer: Texas Instruments; SizeZ_mm: 1.1mm; AEC Qualified: Yes; AEC Grade: Grade 1; Max Supply Voltage: 6V; Min Supply Voltage: 900mV; Nominal Supply Current: 0.25uA; Number Of Outputs: 1; Output Voltage: 0-6V; Reset Type: Active Low; Standoff Height: 0mm; TaMax_C: +125°C; TaMin_C: -40°C; Watchdog Timer: true

## Sheet MCU122A_WM1_ESD.SchDoc
size A3; Date: Not shown in title block; ApprovedBy: Not shown in title block; CheckedBy: Not shown in title block; Author: Not shown in title block; CompanyName: Not shown in title block; Engineer: Not shown in title block; Organization: Not shown in title block; Address1: Not shown in title block; Address2: Not shown in title block; Address3: Not shown in title block; Address4: Not shown in title block; DocumentNumber: 1; Revision: Use project parameter SCH_Rev; SheetNumber: 3; SheetTotal: 8; PageSetup: Record=PageOptions¦CenterHorizontal=True¦CenterVertical=True¦PrintScale=0.69¦XCorrection=1.00¦YCorrection=1.00¦PrintKind=0¦BorderSize=5000000¦LeftOffset=0¦BottomOffset=0¦Orientation=2¦PaperLength=1000¦PaperWidth=1000¦Scale=100¦PaperSource=15¦PrintQuality=600¦MediaType=1¦DitherType=10¦PaperKind=Letter¦PrintScaleMode=1
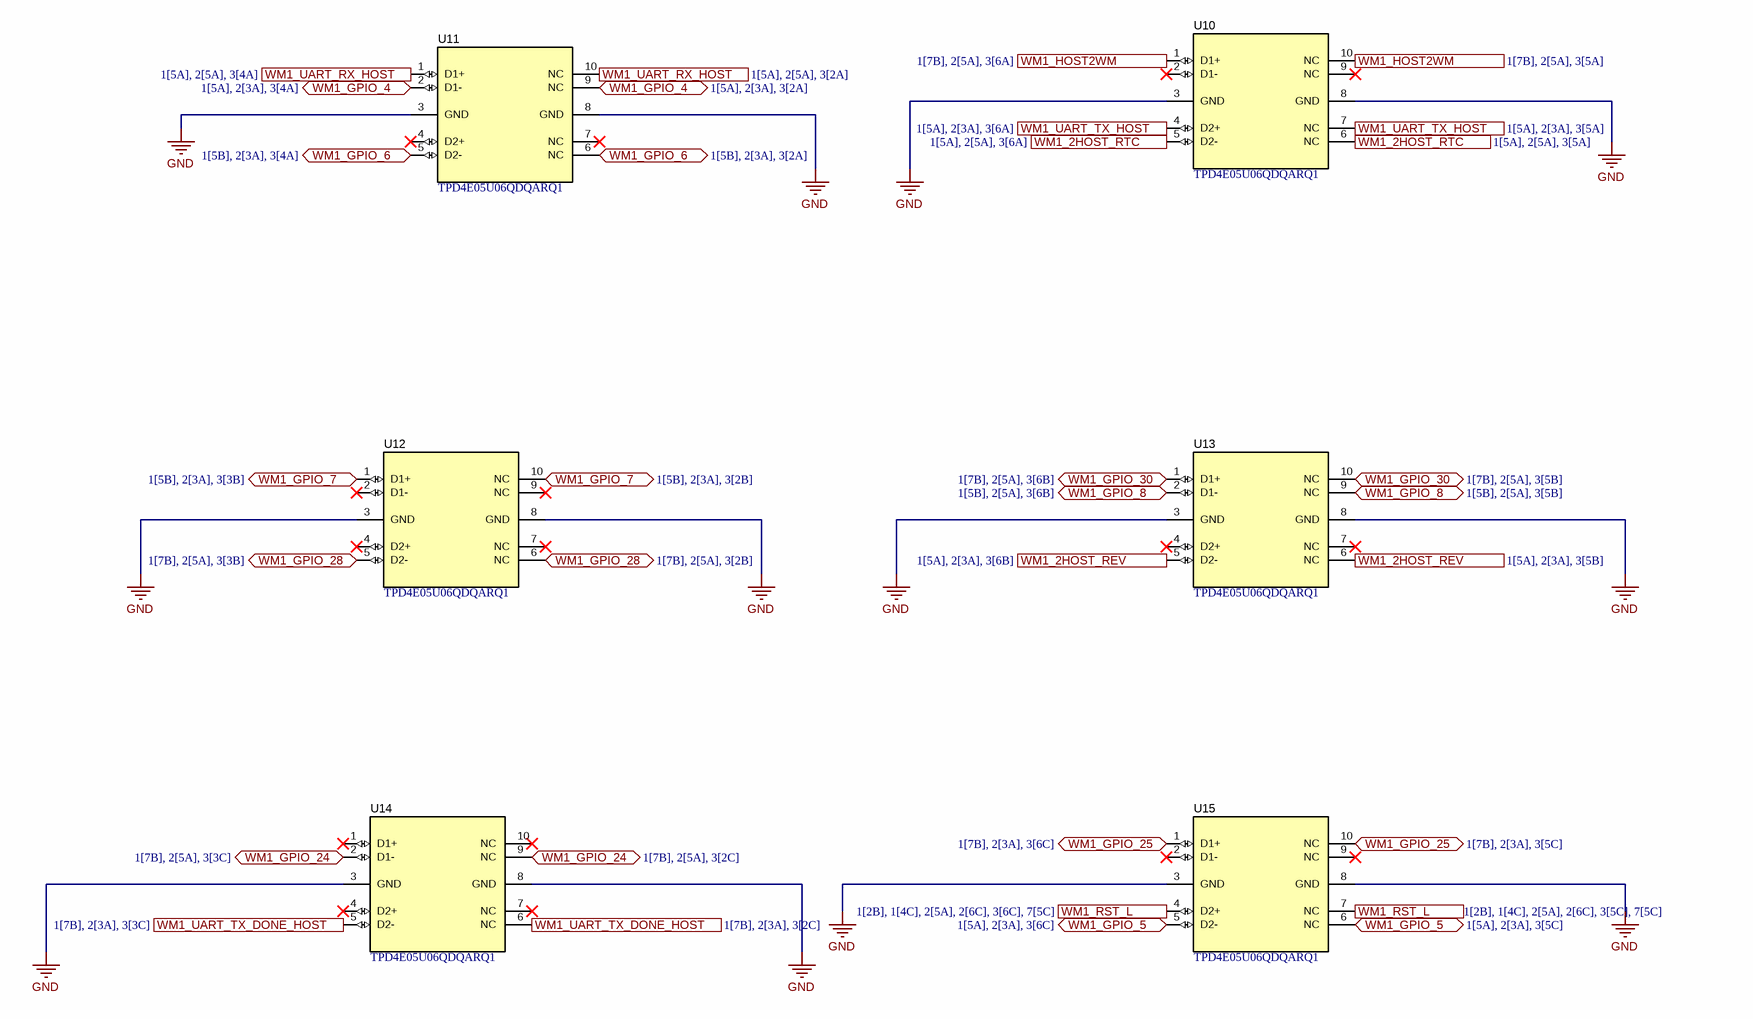
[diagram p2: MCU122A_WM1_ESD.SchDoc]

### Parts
U10  TPD4E05U06QDQARQ1  [DQA0010A]
U11  TPD4E05U06QDQARQ1  [DQA0010A]
U12  TPD4E05U06QDQARQ1  [DQA0010A]
U13  TPD4E05U06QDQARQ1  [DQA0010A]
U14  TPD4E05U06QDQARQ1  [DQA0010A]
U15  TPD4E05U06QDQARQ1  [DQA0010A]

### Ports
WM1_2HOST_REV (out, see 1[5A], 2[3A], 3[5B]), WM1_2HOST_REV (out, see 1[5A], 2[3A], 3[6B]), WM1_2HOST_RTC (out, see 1[5A], 2[5A], 3[5A]), WM1_2HOST_RTC (out, see 1[5A], 2[5A], 3[6A]), WM1_GPIO_4 (bidir, see 1[5A], 2[3A], 3[2A]), WM1_GPIO_4 (bidir, see 1[5A], 2[3A], 3[4A]), WM1_GPIO_5 (bidir, see 1[5A], 2[3A], 3[5C]), WM1_GPIO_5 (bidir, see 1[5A], 2[3A], 3[6C]), WM1_GPIO_6 (bidir, see 1[5B], 2[3A], 3[2A]), WM1_GPIO_6 (bidir, see 1[5B], 2[3A], 3[4A]), WM1_GPIO_7 (bidir, see 1[5B], 2[3A], 3[2B]), WM1_GPIO_7 (bidir, see 1[5B], 2[3A], 3[3B]), WM1_GPIO_8 (bidir, see 1[5B], 2[5A], 3[5B]), WM1_GPIO_8 (bidir, see 1[5B], 2[5A], 3[6B]), WM1_GPIO_24 (bidir, see 1[7B], 2[5A], 3[2C]), WM1_GPIO_24 (bidir, see 1[7B], 2[5A], 3[3C]), WM1_GPIO_25 (bidir, see 1[7B], 2[3A], 3[5C]), WM1_GPIO_25 (bidir, see 1[7B], 2[3A], 3[6C]), WM1_GPIO_28 (bidir, see 1[7B], 2[5A], 3[2B]), WM1_GPIO_28 (bidir, see 1[7B], 2[5A], 3[3B]), WM1_GPIO_30 (bidir, see 1[7B], 2[5A], 3[5B]), WM1_GPIO_30 (bidir, see 1[7B], 2[5A], 3[6B]), WM1_HOST2WM (out, see 1[7B], 2[5A], 3[5A]), WM1_HOST2WM (out, see 1[7B], 2[5A], 3[6A]), WM1_RST_L (out, see 1[2B], 1[4C], 2[5A], 2[6C], 3[5C], 7[5C]), WM1_RST_L (out, see 1[2B], 1[4C], 2[5A], 2[6C], 3[6C], 7[5C]), WM1_UART_RX_HOST (out, see 1[5A], 2[5A], 3[2A]), WM1_UART_RX_HOST (out, see 1[5A], 2[5A], 3[4A]), WM1_UART_TX_DONE_HOST (out, see 1[7B], 2[3A], 3[2C]), WM1_UART_TX_DONE_HOST (out, see 1[7B], 2[3A], 3[3C]), WM1_UART_TX_HOST (out, see 1[5A], 2[3A], 3[5A]), WM1_UART_TX_HOST (out, see 1[5A], 2[3A], 3[6A])

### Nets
GND: U10.3(GND) U10.8(GND) U11.3(GND) U11.8(GND) U12.3(GND) U12.8(GND) U13.3(GND) U13.8(GND) U14.3(GND) U14.8(GND) U15.3(GND) U15.8(GND)
WM1_2HOST_REV: U13.5(D2-) U13.6(NC) ; port WM1_2HOST_REV
WM1_2HOST_RTC: U10.5(D2-) U10.6(NC) ; port WM1_2HOST_RTC
WM1_GPIO_4: U11.2(D1-) U11.9(NC) ; port WM1_GPIO_4
WM1_GPIO_5: U15.5(D2-) U15.6(NC) ; port WM1_GPIO_5
WM1_GPIO_6: U11.5(D2-) U11.6(NC) ; port WM1_GPIO_6
WM1_GPIO_7: U12.1(D1+) U12.10(NC) ; port WM1_GPIO_7
WM1_GPIO_8: U13.2(D1-) U13.9(NC) ; port WM1_GPIO_8
WM1_GPIO_24: U14.2(D1-) U14.9(NC) ; port WM1_GPIO_24
WM1_GPIO_25: U15.1(D1+) U15.10(NC) ; port WM1_GPIO_25
WM1_GPIO_28: U12.5(D2-) U12.6(NC) ; port WM1_GPIO_28
WM1_GPIO_30: U13.1(D1+) U13.10(NC) ; port WM1_GPIO_30
WM1_HOST2WM: U10.1(D1+) U10.10(NC) ; port WM1_HOST2WM
WM1_RST_L: U15.4(D2+) U15.7(NC) ; port WM1_RST_L
WM1_UART_RX_HOST: U11.1(D1+) U11.10(NC) ; port WM1_UART_RX_HOST
WM1_UART_TX_DONE_HOST: U14.5(D2-) U14.6(NC) ; port WM1_UART_TX_DONE_HOST
WM1_UART_TX_HOST: U10.4(D2+) U10.7(NC) ; port WM1_UART_TX_HOST

Not connected (* = marked no-connect by the designer): U10 2(D1-)* 9(NC)*; U11 4(D2+)* 7(NC)*; U12 2(D1-)* 4(D2+)* 7(NC)* 9(NC)*; U13 4(D2+)* 7(NC)*; U14 1(D1+)* 4(D2+)* 7(NC)* 10(NC)*; U15 2(D1-)* 9(NC)*

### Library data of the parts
U10-U15 = CMP-0073599-3: as U5 on sheet MCU122A_WM1

## Sheet MCU122A_WM2.SchDoc
size A3; Date: Not shown in title block; ApprovedBy: Not shown in title block; CheckedBy: Not shown in title block; Author: Not shown in title block; CompanyName: Not shown in title block; Engineer: Not shown in title block; Organization: Not shown in title block; Address1: Not shown in title block; Address2: Not shown in title block; Address3: Not shown in title block; Address4: Not shown in title block; DocumentNumber: 1; Revision: Use project parameter SCH_Rev; SheetNumber: 4; SheetTotal: 8; PageSetup: Record=PageOptions¦CenterHorizontal=True¦CenterVertical=True¦PrintScale=0.69¦XCorrection=1.00¦YCorrection=1.00¦PrintKind=0¦BorderSize=5000000¦LeftOffset=0¦BottomOffset=0¦Orientation=2¦PaperLength=1000¦PaperWidth=1000¦Scale=100¦PaperSource=15¦PrintQuality=600¦MediaType=1¦DitherType=10¦PaperKind=Letter¦PrintScaleMode=1
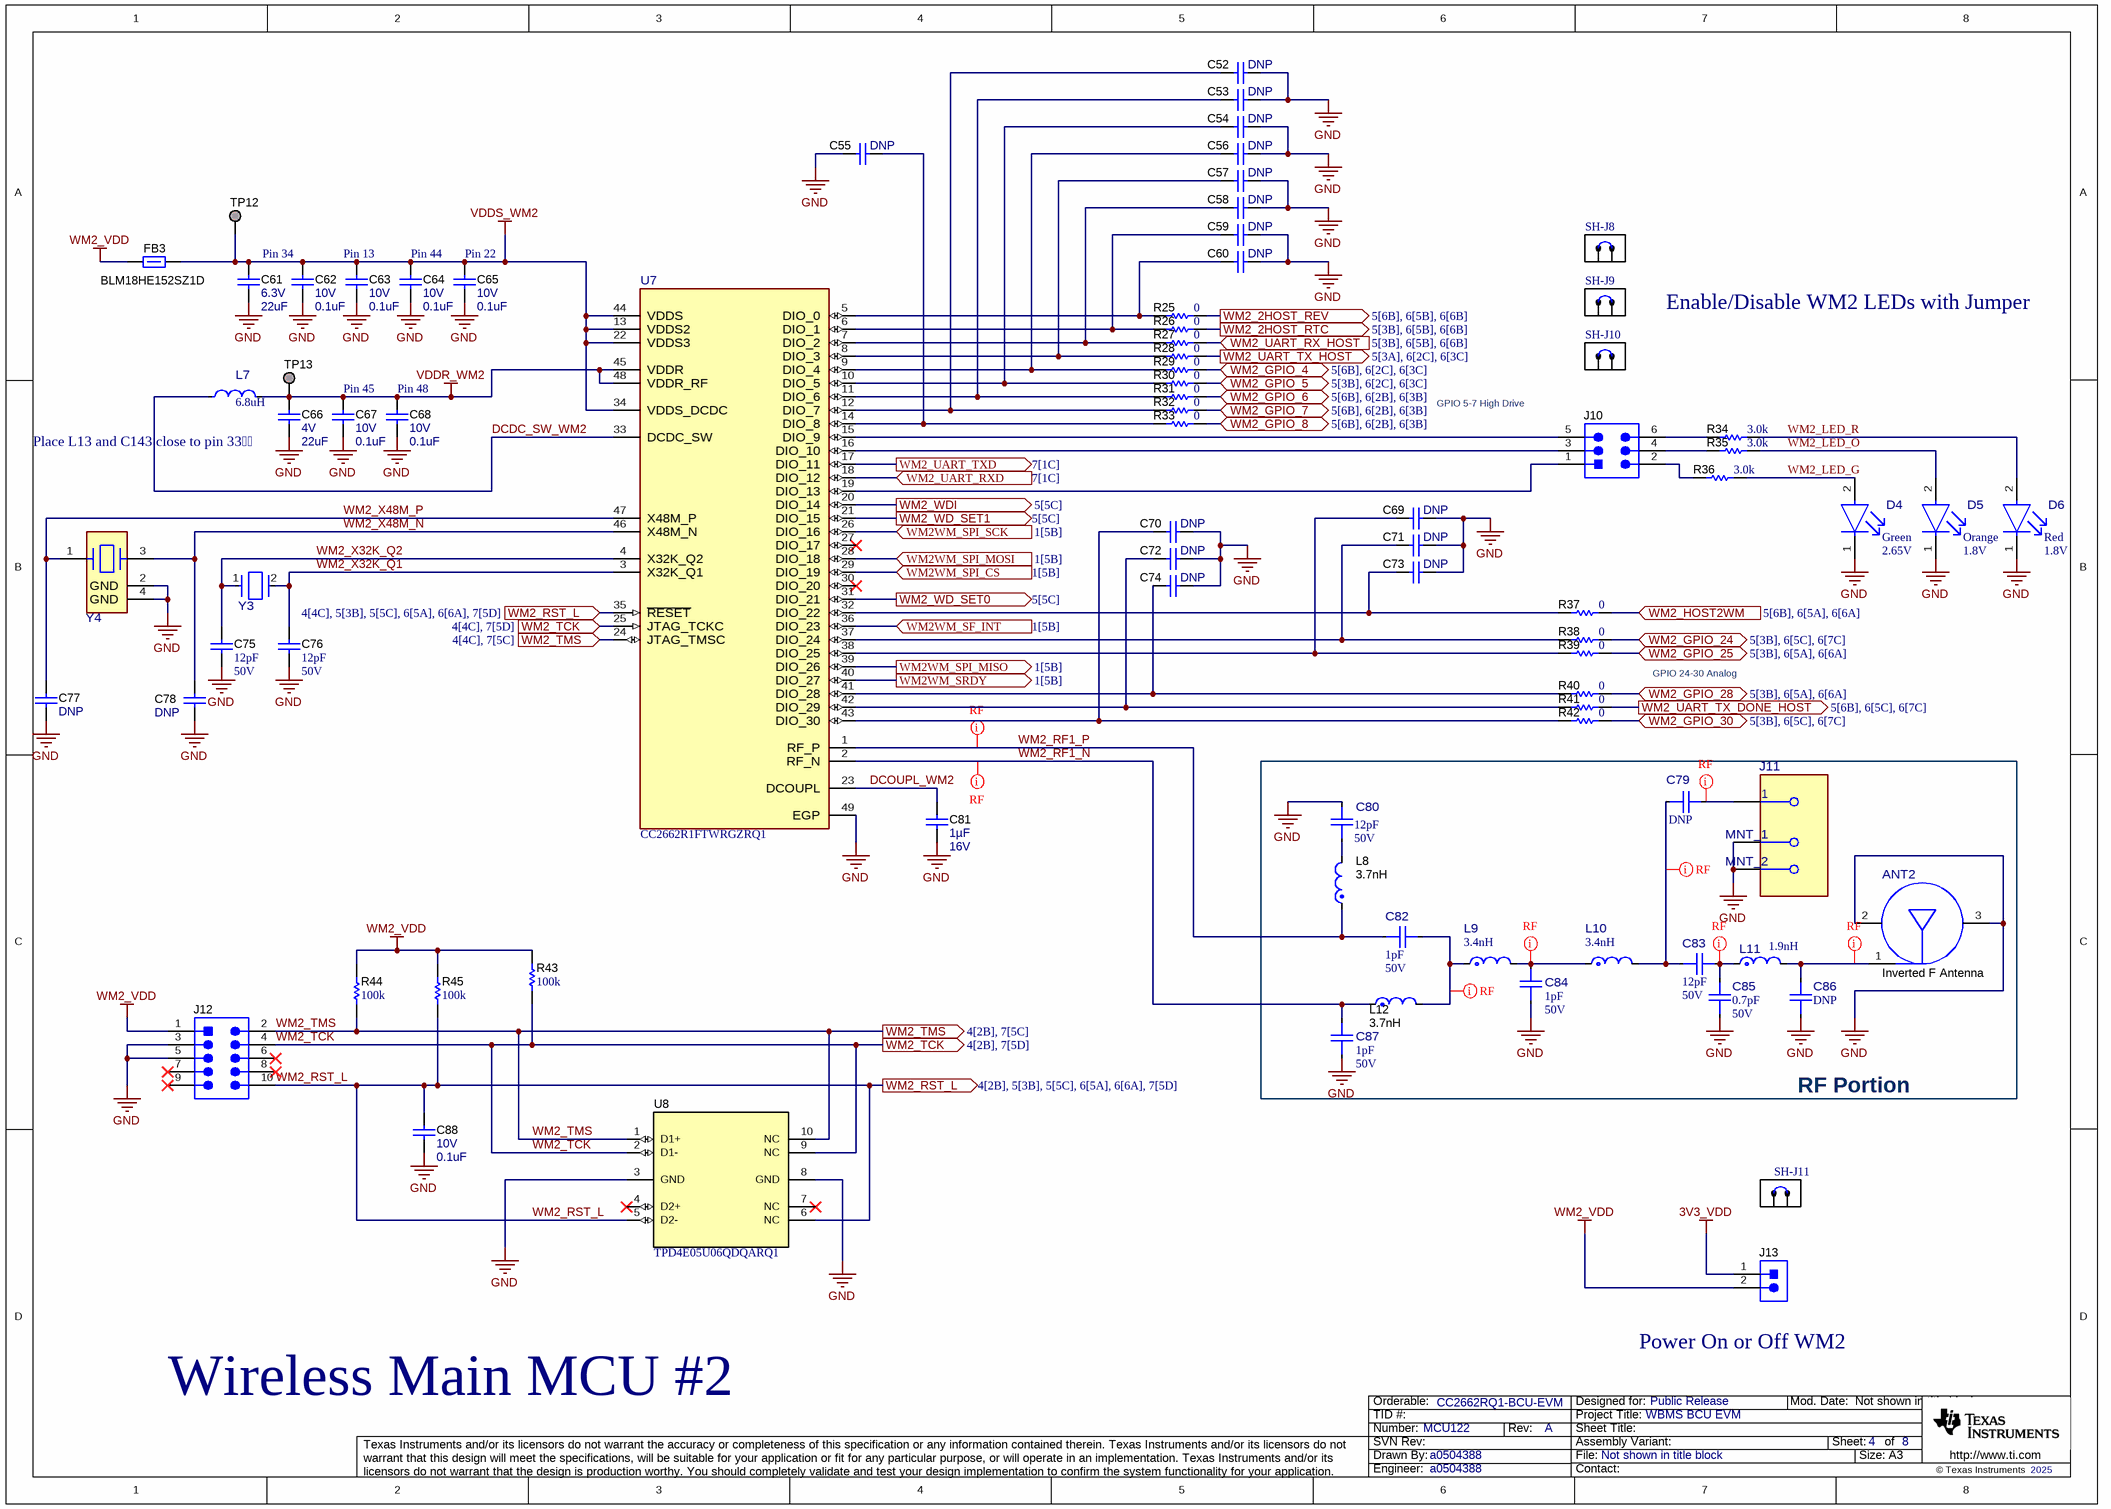
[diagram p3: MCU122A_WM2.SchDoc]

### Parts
ANT2  Inverted F Antenna  [0-MFG]
C52  ValueDisplayed: DNP  [0402]  (hidden comment: GCM155R71A104KA55D)
C53  ValueDisplayed: DNP  [0402]  (hidden comment: GCM155R71A104KA55D)
C54  ValueDisplayed: DNP  [0402]  (hidden comment: GCM155R71A104KA55D)
C55  ValueDisplayed: DNP  [0402]  (hidden comment: GCM155R71A104KA55D)
C56  ValueDisplayed: DNP  [0402]  (hidden comment: GCM155R71A104KA55D)
C57  ValueDisplayed: DNP  [0402]  (hidden comment: GCM155R71A104KA55D)
C58  ValueDisplayed: DNP  [0402]  (hidden comment: GCM155R71A104KA55D)
C59  ValueDisplayed: DNP  [0402]  (hidden comment: GCM155R71A104KA55D)
C60  ValueDisplayed: DNP  [0402]  (hidden comment: GCM155R71A104KA55D)
C61  VDC_V: 6.3V  ValueDisplayed: 22uF  [0805_HV]  (hidden comment: GCM21BD70J226ME36L)
C62  VDC_V: 10V  ValueDisplayed: 0.1uF  [0402]  (hidden comment: GCM155R71A104KA55D)
C63  VDC_V: 10V  ValueDisplayed: 0.1uF  [0402]  (hidden comment: GCM155R71A104KA55D)
C64  VDC_V: 10V  ValueDisplayed: 0.1uF  [0402]  (hidden comment: GCM155R71A104KA55D)
C65  VDC_V: 10V  ValueDisplayed: 0.1uF  [0402]  (hidden comment: GCM155R71A104KA55D)
C66  VDC_V: 4V  ValueDisplayed: 22uF  [0603]  (hidden comment: AMK107BBJ226MAHT)
C67  VDC_V: 10V  ValueDisplayed: 0.1uF  [0402]  (hidden comment: GCM155R71A104KA55D)
C68  VDC_V: 10V  ValueDisplayed: 0.1uF  [0402]  (hidden comment: GCM155R71A104KA55D)
C69  ValueDisplayed: DNP  [0402]  (hidden comment: GCM155R71A104KA55D)
C70  ValueDisplayed: DNP  [0402]  (hidden comment: GCM155R71A104KA55D)
C71  ValueDisplayed: DNP  [0402]  (hidden comment: GCM155R71A104KA55D)
C72  ValueDisplayed: DNP  [0402]  (hidden comment: GCM155R71A104KA55D)
C73  ValueDisplayed: DNP  [0402]  (hidden comment: GCM155R71A104KA55D)
C74  ValueDisplayed: DNP  [0402]  (hidden comment: GCM155R71A104KA55D)
C75  ValueDisplayed: 12pF  VDC_V: 50V  [0402]  (hidden comment: GCM1555C1H120JA16J)
C76  ValueDisplayed: 12pF  VDC_V: 50V  [0402]  (hidden comment: GCM1555C1H120JA16J)
C77  ValueDisplayed: DNP  [0402]  (hidden comment: GCM1555C1H120JA16J)
C78  ValueDisplayed: DNP  [0402]  (hidden comment: GCM1555C1H120JA16J)
C79  ValueDisplayed: DNP  [FP-GCQ0335C1H1R0BB01D_0201-MFG]  (hidden comment: GCQ0335C1H1R0BB01D)
C80  ValueDisplayed: 12pF  VDC_V: 50V  [FP-GCQ0335C1H120GB01D_0201-MFG]  (hidden comment: GCQ0335C1H120GB01D)
C81  Cap_F: 1µF  VDC_V: 16V  [0603]  (hidden comment: GCM188R71C105KA64D)
C82  ValueDisplayed: 1pF  VDC_V: 50V  [FP-GCQ0335C1H1R0WB01D_0201-MFG]  (hidden comment: GCQ0335C1H1R0WB01D)
C83  ValueDisplayed: 12pF  VDC_V: 50V  [FP-GCQ0335C1H120GB01D_0201-MFG]  (hidden comment: GCQ0335C1H120GB01D)
C84  ValueDisplayed: 1pF  VDC_V: 50V  [FP-GCQ0335C1H1R0WB01D_0201-MFG]  (hidden comment: GCQ0335C1H1R0WB01D)
C85  ValueDisplayed: 0.7pF  VDC_V: 50V  [FP-GCQ0335C1HR70WB01D_0201-MFG]  (hidden comment: GCQ0335C1HR70WB01D)
C86  ValueDisplayed: DNP  [FP-GCQ0335C1H1R0BB01D_0201-MFG]  (hidden comment: GCQ0335C1H1R0BB01D)
C87  ValueDisplayed: 1pF  VDC_V: 50V  [FP-GCQ0335C1H1R0WB01D_0201-MFG]  (hidden comment: GCQ0335C1H1R0WB01D)
C88  VDC_V: 10V  ValueDisplayed: 0.1uF  [0402]  (hidden comment: GCM155R71A104KA55D)
D4  Color: Green  Vf_V: 2.65V  [FP-APHHS1005LZGCK-V_0402-MFG]  (hidden comment: APHHS1005LZGCK-V)
D5  Color: Orange  Vf_V: 1.8V  [FP-APHHS1005LSECK/J4-PF_0402-MFG]  (hidden comment: APHHS1005LSECK/J4-PF)
D6  Color: Red  Vf_V: 1.8V  [FP-APHHS1005LSECK/J3-PF_0402-MFG]  (hidden comment: APHHS1005LSECK/J3-PF)
FB3  BLM18HE152SZ1D  [0603]
J10  TSW-103-07-G-D  [TSW-103-07-G-D]  (value not drawn)
J11  132134-10  [FP-132134-10_SMA-MFG]  (value not drawn)
J12  FTSH-105-01-F-DV-K  [Samtec_FTSH-105-01-x-DV-K]  (value not drawn)
J13  TSW-102-07-G-S  [TSW-102-07-G-S]  (value not drawn)
L7  value 6.8uH  [FP-MLZ2012N6R8LTD25_0805-MFG]  (hidden comment: MLZ2012N6R8LTD25)
L8  value 3.7nH  [FP-LQP03TN3N7BZ2J_0603-MFG]  (hidden comment: LQP03TN3N7BZ2J)
L9  value 3.4nH  [FP-LQP03TN3N4BZ2B_0201 (0603)-MFG]  (hidden comment: LQP03TN3N4BZ2B)
L10  value 3.4nH  [FP-LQP03TN3N4BZ2B_0201 (0603)-MFG]  (hidden comment: LQP03TN3N4BZ2B)
L11  value 1.9nH  [FP-LQP03TN1N9BZ2B_0201 (0603)-MFG]  (hidden comment: LQP03TN1N9BZ2B)
L12  value 3.7nH  [FP-LQP03TN3N7BZ2J_0603-MFG]  (hidden comment: LQP03TN3N7BZ2J)
R25  ValueDisplayed: 0  [0402]  (hidden comment: CRCW04020000Z0ED)
R26  ValueDisplayed: 0  [0402]  (hidden comment: CRCW04020000Z0ED)
R27  ValueDisplayed: 0  [0402]  (hidden comment: CRCW04020000Z0ED)
R28  ValueDisplayed: 0  [0402]  (hidden comment: CRCW04020000Z0ED)
R29  ValueDisplayed: 0  [0402]  (hidden comment: CRCW04020000Z0ED)
R30  ValueDisplayed: 0  [0402]  (hidden comment: CRCW04020000Z0ED)
R31  ValueDisplayed: 0  [0402]  (hidden comment: CRCW04020000Z0ED)
R32  ValueDisplayed: 0  [0402]  (hidden comment: CRCW04020000Z0ED)
R33  ValueDisplayed: 0  [0402]  (hidden comment: CRCW04020000Z0ED)
R34  ValueDisplayed: 3.0k  [0402]  (hidden comment: CRCW04023K00JNED)
R35  ValueDisplayed: 3.0k  [0402]  (hidden comment: CRCW04023K00JNED)
R36  ValueDisplayed: 3.0k  [0402]  (hidden comment: CRCW04023K00JNED)
R37  ValueDisplayed: 0  [0402]  (hidden comment: CRCW04020000Z0ED)
R38  ValueDisplayed: 0  [0402]  (hidden comment: CRCW04020000Z0ED)
R39  ValueDisplayed: 0  [0402]  (hidden comment: CRCW04020000Z0ED)
R40  ValueDisplayed: 0  [0402]  (hidden comment: CRCW04020000Z0ED)
R41  ValueDisplayed: 0  [0402]  (hidden comment: CRCW04020000Z0ED)
R42  ValueDisplayed: 0  [0402]  (hidden comment: CRCW04020000Z0ED)
R43  ValueDisplayed: 100k  [0402]  (hidden comment: AC0402FR-07100KL)
R44  ValueDisplayed: 100k  [0402]  (hidden comment: AC0402FR-07100KL)
R45  ValueDisplayed: 100k  [0402]  (hidden comment: AC0402FR-07100KL)
SH-J8  SNT-100-BK-G  [SNT-100-BK-G]  (value not drawn)
SH-J9  SNT-100-BK-G  [SNT-100-BK-G]  (value not drawn)
SH-J10  SNT-100-BK-G  [SNT-100-BK-G]  (value not drawn)
SH-J11  SNT-100-BK-G  [SNT-100-BK-G]  (value not drawn)
TP12  TP_SM_1MM  [TP_SM_1MM]  (value not drawn)  (no BOM)
TP13  TP_SM_1MM  [TP_SM_1MM]  (value not drawn)  (no BOM)
U7  CC2662R1FTWRGZRQ1  [RGZ0048R-MFG]
U8  TPD4E05U06QDQARQ1  [DQA0010A]
Y3  DST1610A 7BG03276AAC  [FP-DST1610A 7BG03276AAC_SMD2-MFG]  (value not drawn)
Y4  CX2016DB48000C0FRLC1  [FP-CX2016DB48000C0FRLC1_SMT4_2MM05_1MM65-MFG]  (value not drawn)

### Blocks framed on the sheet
RF Portion: ANT2 C79 C80 C82-C87 J11 L8-L12

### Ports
WM2_2HOST_REV (out, see 5[6B], 6[5B], 6[6B]), WM2_2HOST_RTC (out, see 5[3B], 6[5B], 6[6B]), WM2_GPIO_4 (bidir, see 5[6B], 6[2C], 6[3C]), WM2_GPIO_5 (bidir, see 5[3B], 6[2C], 6[3C]), WM2_GPIO_6 (bidir, see 5[6B], 6[2B], 6[3B]), WM2_GPIO_7 (bidir, see 5[6B], 6[2B], 6[3B]), WM2_GPIO_8 (bidir, see 5[6B], 6[2B], 6[3B]), WM2_GPIO_24 (bidir, see 5[3B], 6[5C], 6[7C]), WM2_GPIO_25 (bidir, see 5[3B], 6[5A], 6[6A]), WM2_GPIO_28 (bidir, see 5[3B], 6[5A], 6[6A]), WM2_GPIO_30 (bidir, see 5[3B], 6[5C], 6[7C]), WM2_HOST2WM (in, see 5[6B], 6[5A], 6[6A]), WM2_RST_L (in, see 4[4C], 5[3B], 5[5C], 6[5A], 6[6A], 7[5D]), WM2_RST_L (out, see 4[2B], 5[3B], 5[5C], 6[5A], 6[6A], 7[5D]), WM2_TCK (in, see 4[4C], 7[5D]), WM2_TCK (out, see 4[2B], 7[5D]), WM2_TMS (in, see 4[4C], 7[5C]), WM2_TMS (out, see 4[2B], 7[5C]), WM2_UART_RX_HOST (in, see 5[3B], 6[5B], 6[6B]), WM2_UART_RXD (in, see 7[1C]), WM2_UART_TX_DONE_HOST (out, see 5[6B], 6[5C], 6[7C]), WM2_UART_TX_HOST (out, see 5[3A], 6[2C], 6[3C]), WM2_UART_TXD (out, see 7[1C]), WM2_WD_SET0 (out, see 5[5C]), WM2_WD_SET1 (out, see 5[5C]), WM2_WDI (out, see 5[5C]), WM2WM_SF_INT (in, see 1[5B]), WM2WM_SPI_CS (in, see 1[5B]), WM2WM_SPI_MISO (out, see 1[5B]), WM2WM_SPI_MOSI (in, see 1[5B]), WM2WM_SPI_SCK (in, see 1[5B]), WM2WM_SRDY (out, see 1[5B])

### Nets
3V3_VDD: J13.1
GND: ANT2.2(GND) ANT2.3(GND) C52.1 C53.1 C54.1 C55.2 C56.1 C57.1 C58.1 C59.1 C60.1 C61.2 C62.2 C63.2 C64.2 C65.2 C66.2 C67.2 C68.2 C69.1 C70.1 C71.1 C72.1 C73.1 C74.1 C75.2 C76.2 C77.2 C78.2 C80.2 C81.2 C84.1 C85.1 C86.1 C87.1 C88.2 D4.1(CATHODE) D5.1(CATHODE) D6.1(CATHODE) J11.2(MNT_1) J11.3(MNT_2) J12.3 J12.5 U7.49(EGP) U8.3(GND) U8.8(GND) Y4.2(GND) Y4.4(GND)
VDDR_WM2: C66.1 C67.1 C68.1 L7.2 TP13.1 U7.45(VDDR) U7.48(VDDR_RF)
VDDS_WM2: C61.1 C62.1 C63.1 C64.1 C65.1 FB3.2 TP12.1 U7.13(VDDS2) U7.22(VDDS3) U7.34(VDDS_DCDC) U7.44(VDDS)
WM2_VDD: FB3.1 J12.1 J13.2 R43.2 R44.2 R45.2
DCDC_SW_WM2: L7.1 U7.33(DCDC_SW)
DCOUPL_WM2: C81.1 U7.23(DCOUPL)
WM2_2HOST_REV: R25.2 ; port WM2_2HOST_REV
WM2_2HOST_RTC: R26.2 ; port WM2_2HOST_RTC
WM2_GPIO_4: R29.2 ; port WM2_GPIO_4
WM2_GPIO_5: R30.2 ; port WM2_GPIO_5
WM2_GPIO_6: R31.2 ; port WM2_GPIO_6
WM2_GPIO_7: R32.2 ; port WM2_GPIO_7
WM2_GPIO_8: R33.2 ; port WM2_GPIO_8
WM2_GPIO_24: R38.2 ; port WM2_GPIO_24
WM2_GPIO_25: R39.2 ; port WM2_GPIO_25
WM2_GPIO_28: R40.2 ; port WM2_GPIO_28
WM2_GPIO_30: R42.2 ; port WM2_GPIO_30
WM2_HOST2WM: R37.2 ; port WM2_HOST2WM
WM2_LED_G: D4.2(ANODE) R36.2
WM2_LED_O: D5.2(ANODE) R35.2
WM2_LED_R: D6.2(ANODE) R34.2
WM2_RF1_N: C87.2 L12.1 U7.2(RF_N)
WM2_RF1_P: C82.1 L8.1 U7.1(RF_P)
WM2_RST_L: C88.1 J12.10 R45.1 U7.35(~{RESET}) U8.5(D2-) U8.6(NC) ; port WM2_RST_L
WM2_TCK: J12.4 R43.1 U7.25(JTAG_TCKC) U8.2(D1-) U8.9(NC) ; port WM2_TCK
WM2_TMS: J12.2 R44.1 U7.24(JTAG_TMSC) U8.1(D1+) U8.10(NC) ; port WM2_TMS
WM2_UART_RX_HOST: R27.2 ; port WM2_UART_RX_HOST
WM2_UART_RXD: U7.18(DIO_12) ; port WM2_UART_RXD
WM2_UART_TX_DONE_HOST: R41.2 ; port WM2_UART_TX_DONE_HOST
WM2_UART_TX_HOST: R28.2 ; port WM2_UART_TX_HOST
WM2_UART_TXD: U7.17(DIO_11) ; port WM2_UART_TXD
WM2_WD_SET0: U7.31(DIO_21) ; port WM2_WD_SET0
WM2_WD_SET1: U7.21(DIO_15) ; port WM2_WD_SET1
WM2_WDI: U7.20(DIO_14) ; port WM2_WDI
WM2_X32K_Q1: C76.1 U7.3(X32K_Q1) Y3.2
WM2_X32K_Q2: C75.1 U7.4(X32K_Q2) Y3.1
WM2_X48M_N: C78.1 U7.46(X48M_N) Y4.3
WM2_X48M_P: C77.1 U7.47(X48M_P) Y4.1
WM2WM_SF_INT: U7.36(DIO_23) ; port WM2WM_SF_INT
WM2WM_SPI_CS: U7.29(DIO_19) ; port WM2WM_SPI_CS
WM2WM_SPI_MISO: U7.39(DIO_26) ; port WM2WM_SPI_MISO
WM2WM_SPI_MOSI: U7.28(DIO_18) ; port WM2WM_SPI_MOSI
WM2WM_SPI_SCK: U7.26(DIO_16) ; port WM2WM_SPI_SCK
WM2WM_SRDY: U7.40(DIO_27) ; port WM2WM_SRDY
NetANT2_1: ANT2.1(Feed) C86.2 L11.2
NetC52_2: C52.2 R32.1 U7.12(DIO_7)
NetC53_2: C53.2 R31.1 U7.11(DIO_6)
NetC54_2: C54.2 R30.1 U7.10(DIO_5)
NetC55_1: C55.1 R33.1 U7.14(DIO_8)
NetC56_2: C56.2 R29.1 U7.9(DIO_4)
NetC57_2: C57.2 R28.1 U7.8(DIO_3)
NetC58_2: C58.2 R27.1 U7.7(DIO_2)
NetC59_2: C59.2 R26.1 U7.6(DIO_1)
NetC60_2: C60.2 R25.1 U7.5(DIO_0)
NetC69_2: C69.2 R39.1 U7.38(DIO_25)
NetC70_2: C70.2 R42.1 U7.43(DIO_30)
NetC71_2: C71.2 R38.1 U7.37(DIO_24)
NetC72_2: C72.2 R41.1 U7.42(DIO_29)
NetC73_2: C73.2 R37.1 U7.32(DIO_22)
NetC74_2: C74.2 R40.1 U7.41(DIO_28)
NetC79_1: C79.1 C83.1 L10.2
NetC79_2: C79.2 J11.1
NetC80_1: C80.1 L8.2
NetC82_2: C82.2 L9.1 L12.2
NetC83_2: C83.2 C85.2 L11.1
NetC84_2: C84.2 L9.2 L10.1
NetJ10_1: J10.1 U7.19(DIO_13)
NetJ10_2: J10.2 R36.1
NetJ10_3: J10.3 U7.16(DIO_10)
NetJ10_4: J10.4 R35.1
NetJ10_5: J10.5 U7.15(DIO_9)
NetJ10_6: J10.6 R34.1

Not connected (* = marked no-connect by the designer): J12 6* 7* 8* 9*; U7 27(DIO_17)* 30(DIO_20)*; U8 4(D2+)* 7(NC)*

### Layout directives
net class RF: NetANT2_1, NetC79_1, NetC79_2, NetC82_2, NetC83_2, NetC84_2, WM2_RF1_N, WM2_RF1_P

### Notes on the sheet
- Pin 34
- (near C63) Pin 13
- Pin 44
- (near C65) Pin 22
- Enable/Disable WM2 LEDs with Jumper
- (near C66) Place L13 and C143 close to pin 33
- Pin 45
- (near C68) Pin 48
- GPIO 5-7 High Drive
- GPIO 24-30 Analog
- (near J13) Power On or Off WM2
- Wireless Main MCU #2

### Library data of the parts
ANT2 = CMP-0091830-1: as ANT1 on sheet MCU122A_WM1
C52-C60 C69-C74 = CMP-0006350-2: as C12 on sheet MCU122A_WM1
C61 = CMP-0008015-1: as C21 on sheet MCU122A_WM1
C62-C65 C67 C68 C88 = CMP-0006350-2: as C22 on sheet MCU122A_WM1
C66 = CMP-0064940-5: as C26 on sheet MCU122A_WM1
C75 C76 = CMP-0085816-1: as C35 on sheet MCU122A_WM1
C77 C78 = CMP-0085816-1: as C37 on sheet MCU122A_WM1
C79 C86 = CMP-0037173-1: as C39 on sheet MCU122A_WM1
C80 C83 = CMP-0120430-1: as C40 on sheet MCU122A_WM1
C81 = CMP-0007136-5: as C41 on sheet MCU122A_WM1
C82 C84 C87 = CMP-0120431-1: as C42 on sheet MCU122A_WM1
C85 = CMP-0124488-1: as C45 on sheet MCU122A_WM1
D4 = CMP-0120353-1: as D1 on sheet MCU122A_WM1
D5 = CMP-0120352-1: as D2 on sheet MCU122A_WM1
D6 = CMP-0120351-1: as D3 on sheet MCU122A_WM1
FB3 = CMP-0080768-1: as FB2 on sheet MCU122A_WM1
J10 = CMP-0075406-2: as J3 on sheet MCU122A_WM1
J11 = CMP-0035654-1: as J4 on sheet MCU122A_WM1
J12 = CMP-0075670-2: as J5 on sheet MCU122A_WM1
J13 = CMP-0075405-3: as J6 on sheet MCU122A_WM1
L7 = CMP-0121210-1: as L1 on sheet MCU122A_WM1
L8 L12 = CMP-0090225-1: as L2 on sheet MCU122A_WM1
L9 L10 = CMP-0037178-1: as L3 on sheet MCU122A_WM1
L11 = CMP-0124484-1: as L5 on sheet MCU122A_WM1
R25-R33 R37-R42 = CMP-0026822-3: as R1 on sheet MCU122A_WM1
R34-R36 = CMP-0026917-5: as R10 on sheet MCU122A_WM1
R43-R45 = CMP-0080661-1: as R19 on sheet MCU122A_WM1
SH-J8-SH-J11 = CMP-0003623-3: as SH-J2 on sheet MCU122A_WM1
TP12 TP13 = CMP-0003825-1: 1mm Test Point, SMT; Manufacturer: Any
U7 = CMP-0121950-1: as U1 on sheet MCU122A_WM1
U8 = CMP-0073599-3: as U5 on sheet MCU122A_WM1
Y3 = CMP-0121920-1: as Y1 on sheet MCU122A_WM1
Y4 = CMP-0121714-1: as Y2 on sheet MCU122A_WM1

## Sheet MCU122A_WM2_GPIO_Header.SchDoc
size A3; Date: Not shown in title block; ApprovedBy: Not shown in title block; CheckedBy: Not shown in title block; Author: Not shown in title block; CompanyName: Not shown in title block; Engineer: Not shown in title block; Organization: Not shown in title block; Address1: Not shown in title block; Address2: Not shown in title block; Address3: Not shown in title block; Address4: Not shown in title block; DocumentNumber: 1; Revision: Use project parameter SCH_Rev; SheetNumber: 5; SheetTotal: 8; PageSetup: Record=PageOptions¦CenterHorizontal=True¦CenterVertical=True¦PrintScale=0.69¦XCorrection=1.00¦YCorrection=1.00¦PrintKind=0¦BorderSize=5000000¦LeftOffset=0¦BottomOffset=0¦Orientation=2¦PaperLength=1000¦PaperWidth=1000¦Scale=100¦PaperSource=15¦PrintQuality=600¦MediaType=1¦DitherType=10¦PaperKind=Letter¦PrintScaleMode=1
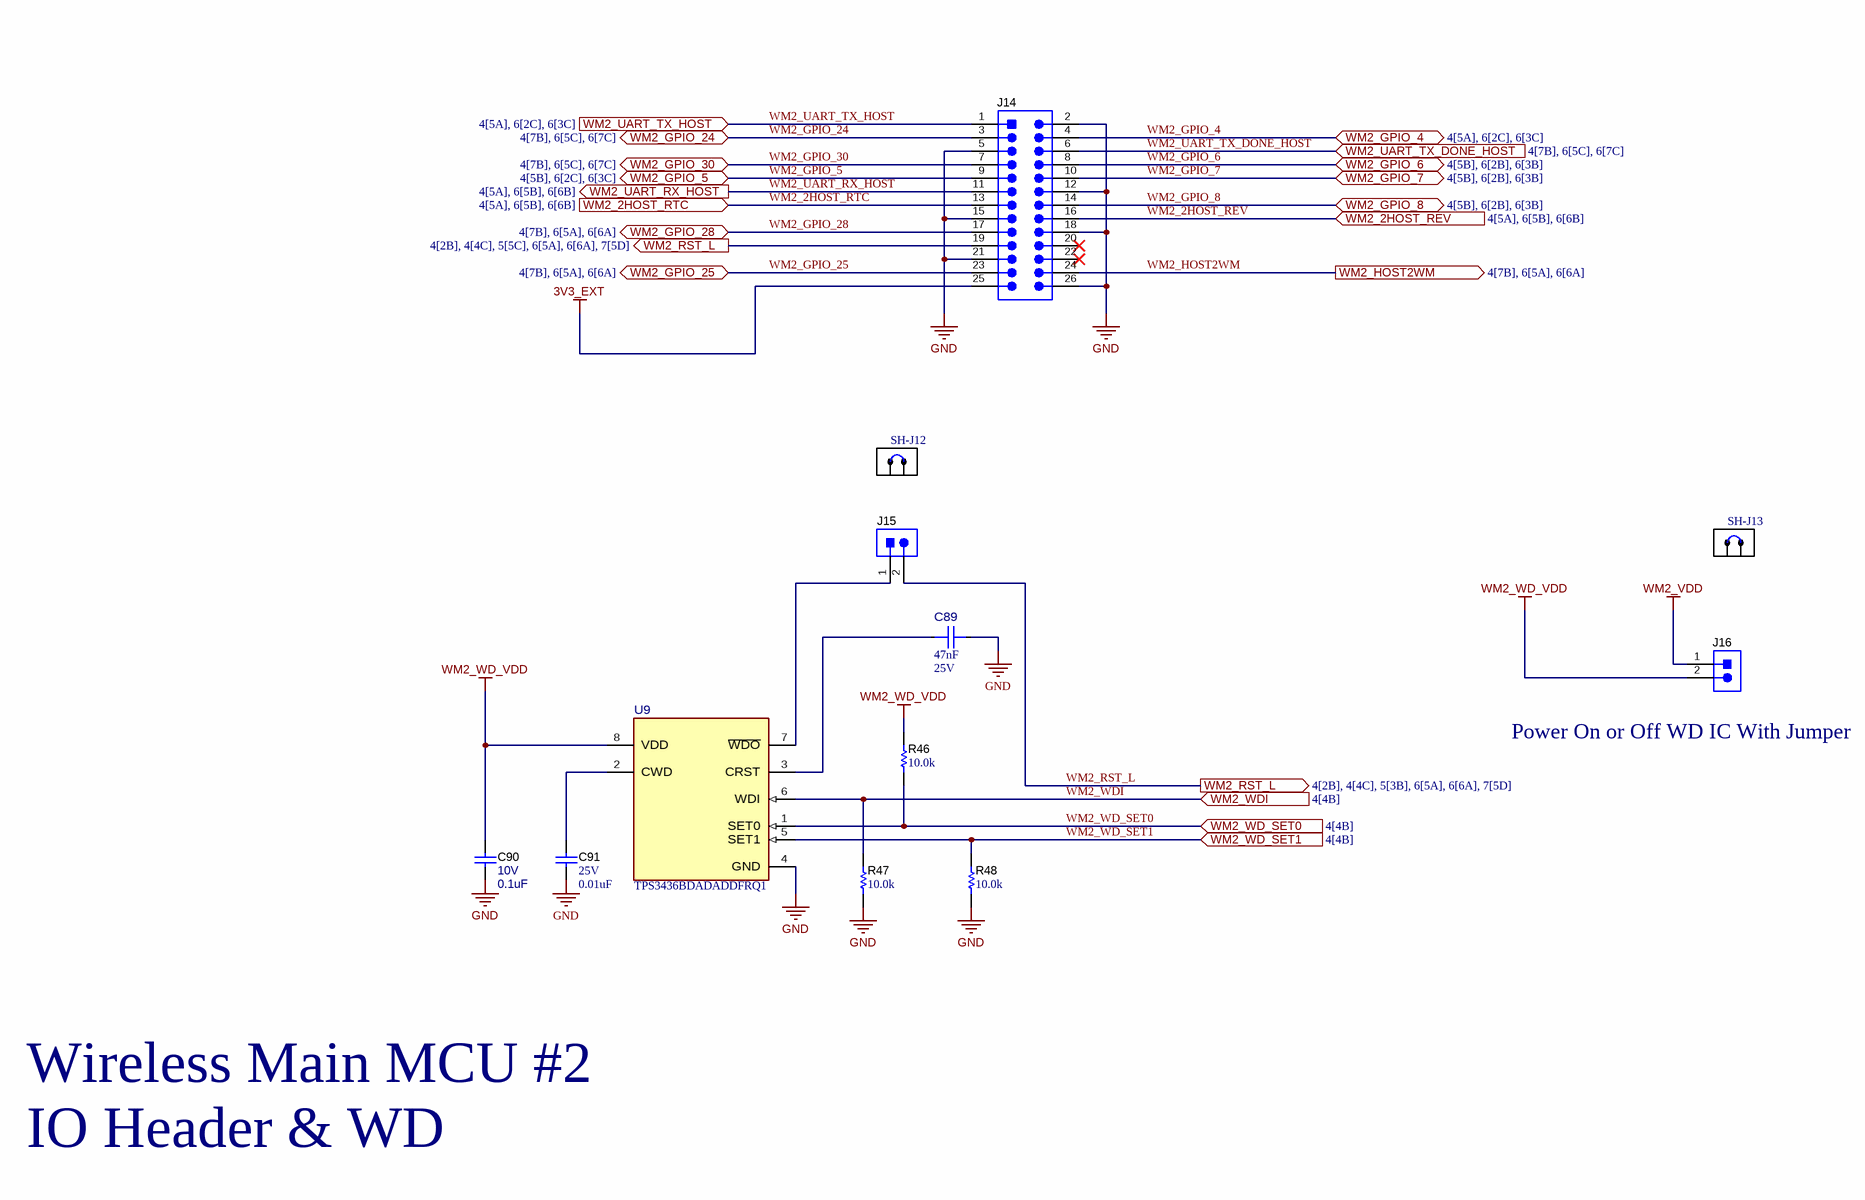
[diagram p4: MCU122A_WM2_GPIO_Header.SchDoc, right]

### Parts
C89  ValueDisplayed: 47nF  VDC_V: 25V  [FP-GCM155R71E473KA55D_0402-MFG]  (hidden comment: GCM155R71E473KA55D)
C90  VDC_V: 10V  ValueDisplayed: 0.1uF  [0402]  (hidden comment: GCM155R71A104KA55D)
C91  VDC_V: 25V  ValueDisplayed: 0.01uF  [0402]  (hidden comment: GCM155R71E103KA37D)
J14  TSW-113-07-G-D  [TSW-113-07-G-D]  (value not drawn)
J15  TSW-102-07-G-S  [TSW-102-07-G-S]  (value not drawn)
J16  TSW-102-07-G-S  [TSW-102-07-G-S]  (value not drawn)
R46  ValueDisplayed: 10.0k  [0402]  (hidden comment: AC0402FR-0710KL)
R47  ValueDisplayed: 10.0k  [0402]  (hidden comment: AC0402FR-0710KL)
R48  ValueDisplayed: 10.0k  [0402]  (hidden comment: AC0402FR-0710KL)
SH-J12  SNT-100-BK-G  [SNT-100-BK-G]  (value not drawn)
SH-J13  SNT-100-BK-G  [SNT-100-BK-G]  (value not drawn)
U9  TPS3436BDADADDFRQ1  [DDF0008A-MFG]

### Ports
WM2_2HOST_REV (in, see 4[5A], 6[5B], 6[6B]), WM2_2HOST_RTC (in, see 4[5A], 6[5B], 6[6B]), WM2_GPIO_4 (bidir, see 4[5A], 6[2C], 6[3C]), WM2_GPIO_5 (bidir, see 4[5B], 6[2C], 6[3C]), WM2_GPIO_6 (bidir, see 4[5B], 6[2B], 6[3B]), WM2_GPIO_7 (bidir, see 4[5B], 6[2B], 6[3B]), WM2_GPIO_8 (bidir, see 4[5B], 6[2B], 6[3B]), WM2_GPIO_24 (bidir, see 4[7B], 6[5C], 6[7C]), WM2_GPIO_25 (bidir, see 4[7B], 6[5A], 6[6A]), WM2_GPIO_28 (bidir, see 4[7B], 6[5A], 6[6A]), WM2_GPIO_30 (bidir, see 4[7B], 6[5C], 6[7C]), WM2_HOST2WM (out, see 4[7B], 6[5A], 6[6A]), WM2_RST_L (out, see 4[2B], 4[4C], 5[3B], 6[5A], 6[6A], 7[5D]), WM2_RST_L (out, see 4[2B], 4[4C], 5[5C], 6[5A], 6[6A], 7[5D]), WM2_UART_RX_HOST (out, see 4[5A], 6[5B], 6[6B]), WM2_UART_TX_DONE_HOST (in, see 4[7B], 6[5C], 6[7C]), WM2_UART_TX_HOST (in, see 4[5A], 6[2C], 6[3C]), WM2_WD_SET0 (in, see 4[4B]), WM2_WD_SET1 (in, see 4[4B]), WM2_WDI (in, see 4[4B])

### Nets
3V3_EXT: J14.25
GND: C89.2 C90.2 C91.2 J14.2 J14.5 J14.12 J14.15 J14.18 J14.21 J14.26 R47.1 R48.1 U9.4(GND)
WM2_VDD: J16.1
WM2_WD_VDD: C90.1 J16.2 R46.2 U9.8(VDD)
WM2_2HOST_REV: J14.16 ; port WM2_2HOST_REV
WM2_2HOST_RTC: J14.13 ; port WM2_2HOST_RTC
WM2_GPIO_4: J14.4 ; port WM2_GPIO_4
WM2_GPIO_5: J14.9 ; port WM2_GPIO_5
WM2_GPIO_6: J14.8 ; port WM2_GPIO_6
WM2_GPIO_7: J14.10 ; port WM2_GPIO_7
WM2_GPIO_8: J14.14 ; port WM2_GPIO_8
WM2_GPIO_24: J14.3 ; port WM2_GPIO_24
WM2_GPIO_25: J14.23 ; port WM2_GPIO_25
WM2_GPIO_28: J14.17 ; port WM2_GPIO_28
WM2_GPIO_30: J14.7 ; port WM2_GPIO_30
WM2_HOST2WM: J14.24 ; port WM2_HOST2WM
WM2_RST_L: J14.19 J15.2 ; port WM2_RST_L
WM2_UART_RX_HOST: J14.11 ; port WM2_UART_RX_HOST
WM2_UART_TX_DONE_HOST: J14.6 ; port WM2_UART_TX_DONE_HOST
WM2_UART_TX_HOST: J14.1 ; port WM2_UART_TX_HOST
WM2_WD_SET0: R46.1 U9.1(SET0) ; port WM2_WD_SET0
WM2_WD_SET1: R48.2 U9.5(SET1) ; port WM2_WD_SET1
WM2_WDI: R47.2 U9.6(WDI) ; port WM2_WDI
NetC89_1: C89.1 U9.3(CRST)
NetC91_1: C91.1 U9.2(CWD)
NetJ15_1: J15.1 U9.7(~{WDO})

Not connected (* = marked no-connect by the designer): J14 20* 22*

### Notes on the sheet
- (near J16) Power On or Off WD IC With Jumper
- Wireless Main MCU #2 IO Header & WD

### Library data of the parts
C89 = CMP-0120705-1: as C49 on sheet MCU122A_WM1_GPIO_Header
C90 = CMP-0006350-2: as C22 on sheet MCU122A_WM1
C91 = CMP-0006352-2: as C51 on sheet MCU122A_WM1_GPIO_Header
J14 = CMP-0075425-1: as J7 on sheet MCU122A_WM1_GPIO_Header
J15 J16 = CMP-0075405-3: as J6 on sheet MCU122A_WM1
R46-R48 = CMP-0077731-1: as R22 on sheet MCU122A_WM1_GPIO_Header
SH-J12 SH-J13 = CMP-0003623-3: as SH-J2 on sheet MCU122A_WM1
U9 = CMP-0120735-1: as U6 on sheet MCU122A_WM1_GPIO_Header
